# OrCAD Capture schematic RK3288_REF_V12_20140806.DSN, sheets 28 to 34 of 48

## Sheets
28 51.LCM-MIPI Panel (option): size A4; title: LCM-MIPI Panel (option); note: LCM-MIPI Panel (option)
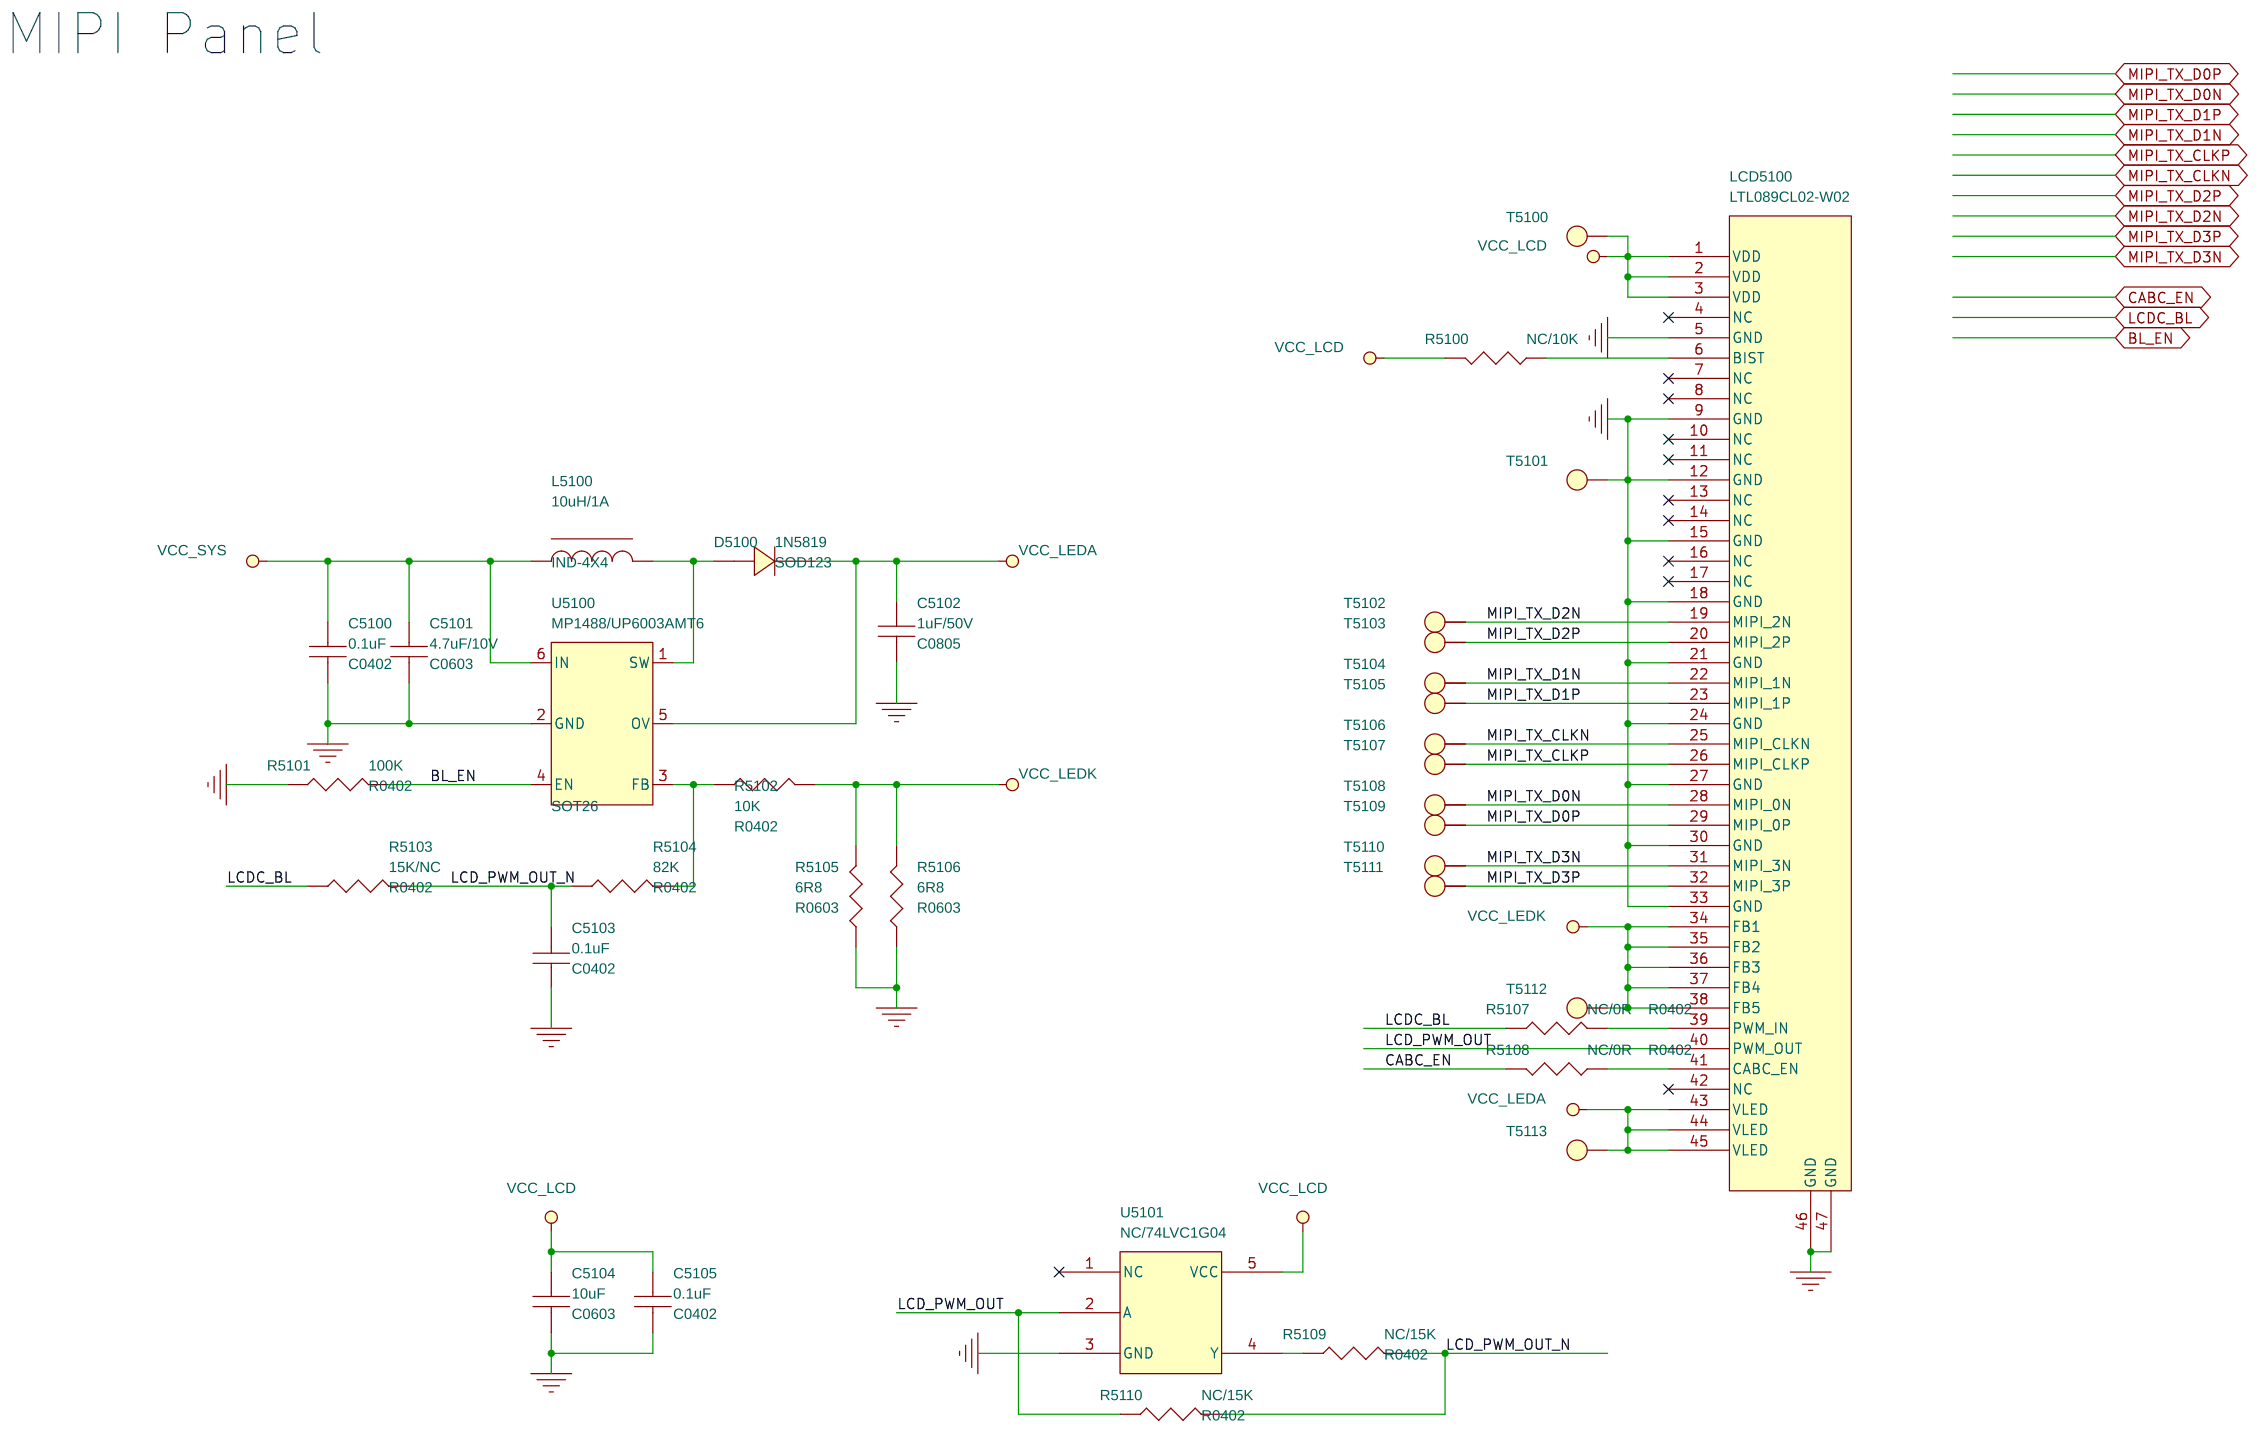
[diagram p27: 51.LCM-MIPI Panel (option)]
29 52.LCM-Dual MIPI Panel (option): size A4; title: LCM-Dual MIPI Panel (option); note: LCM-Dual MIPI Panel (option)
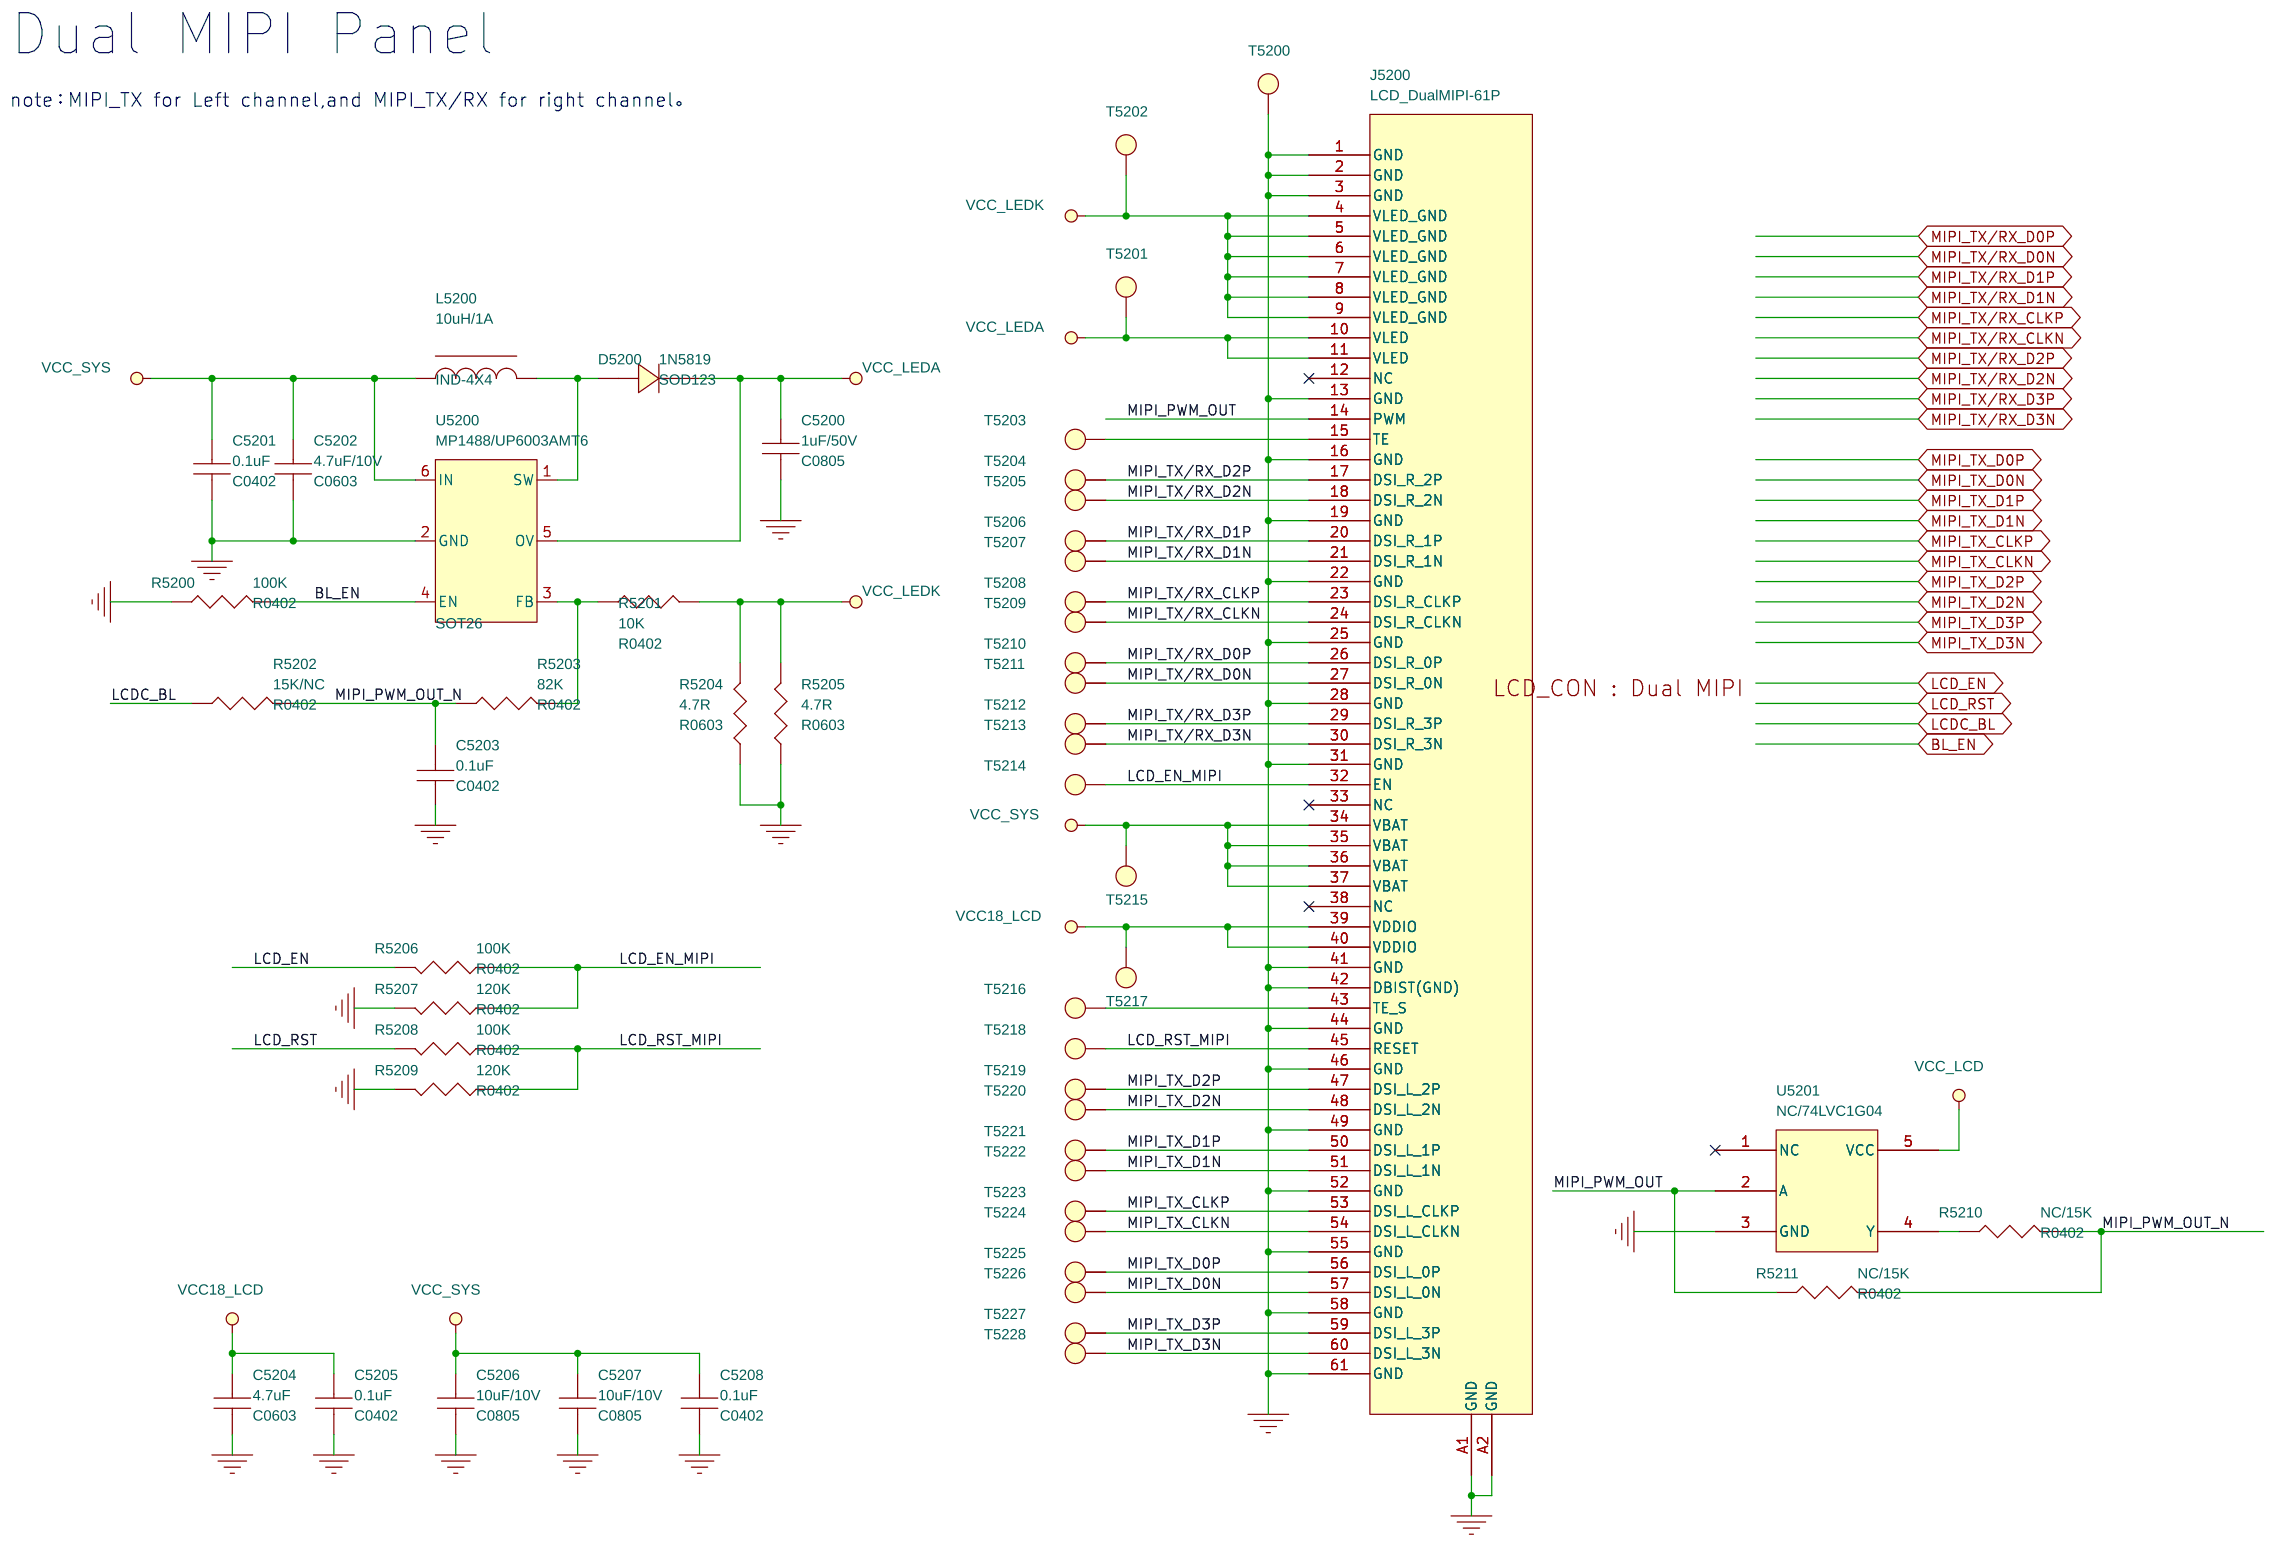
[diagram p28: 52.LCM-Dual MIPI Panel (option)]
30 53.LCM-LVDS Panel (option): size A4; title: LCM-LVDS Panel (option); note: LCM-LVDS Panel (option)
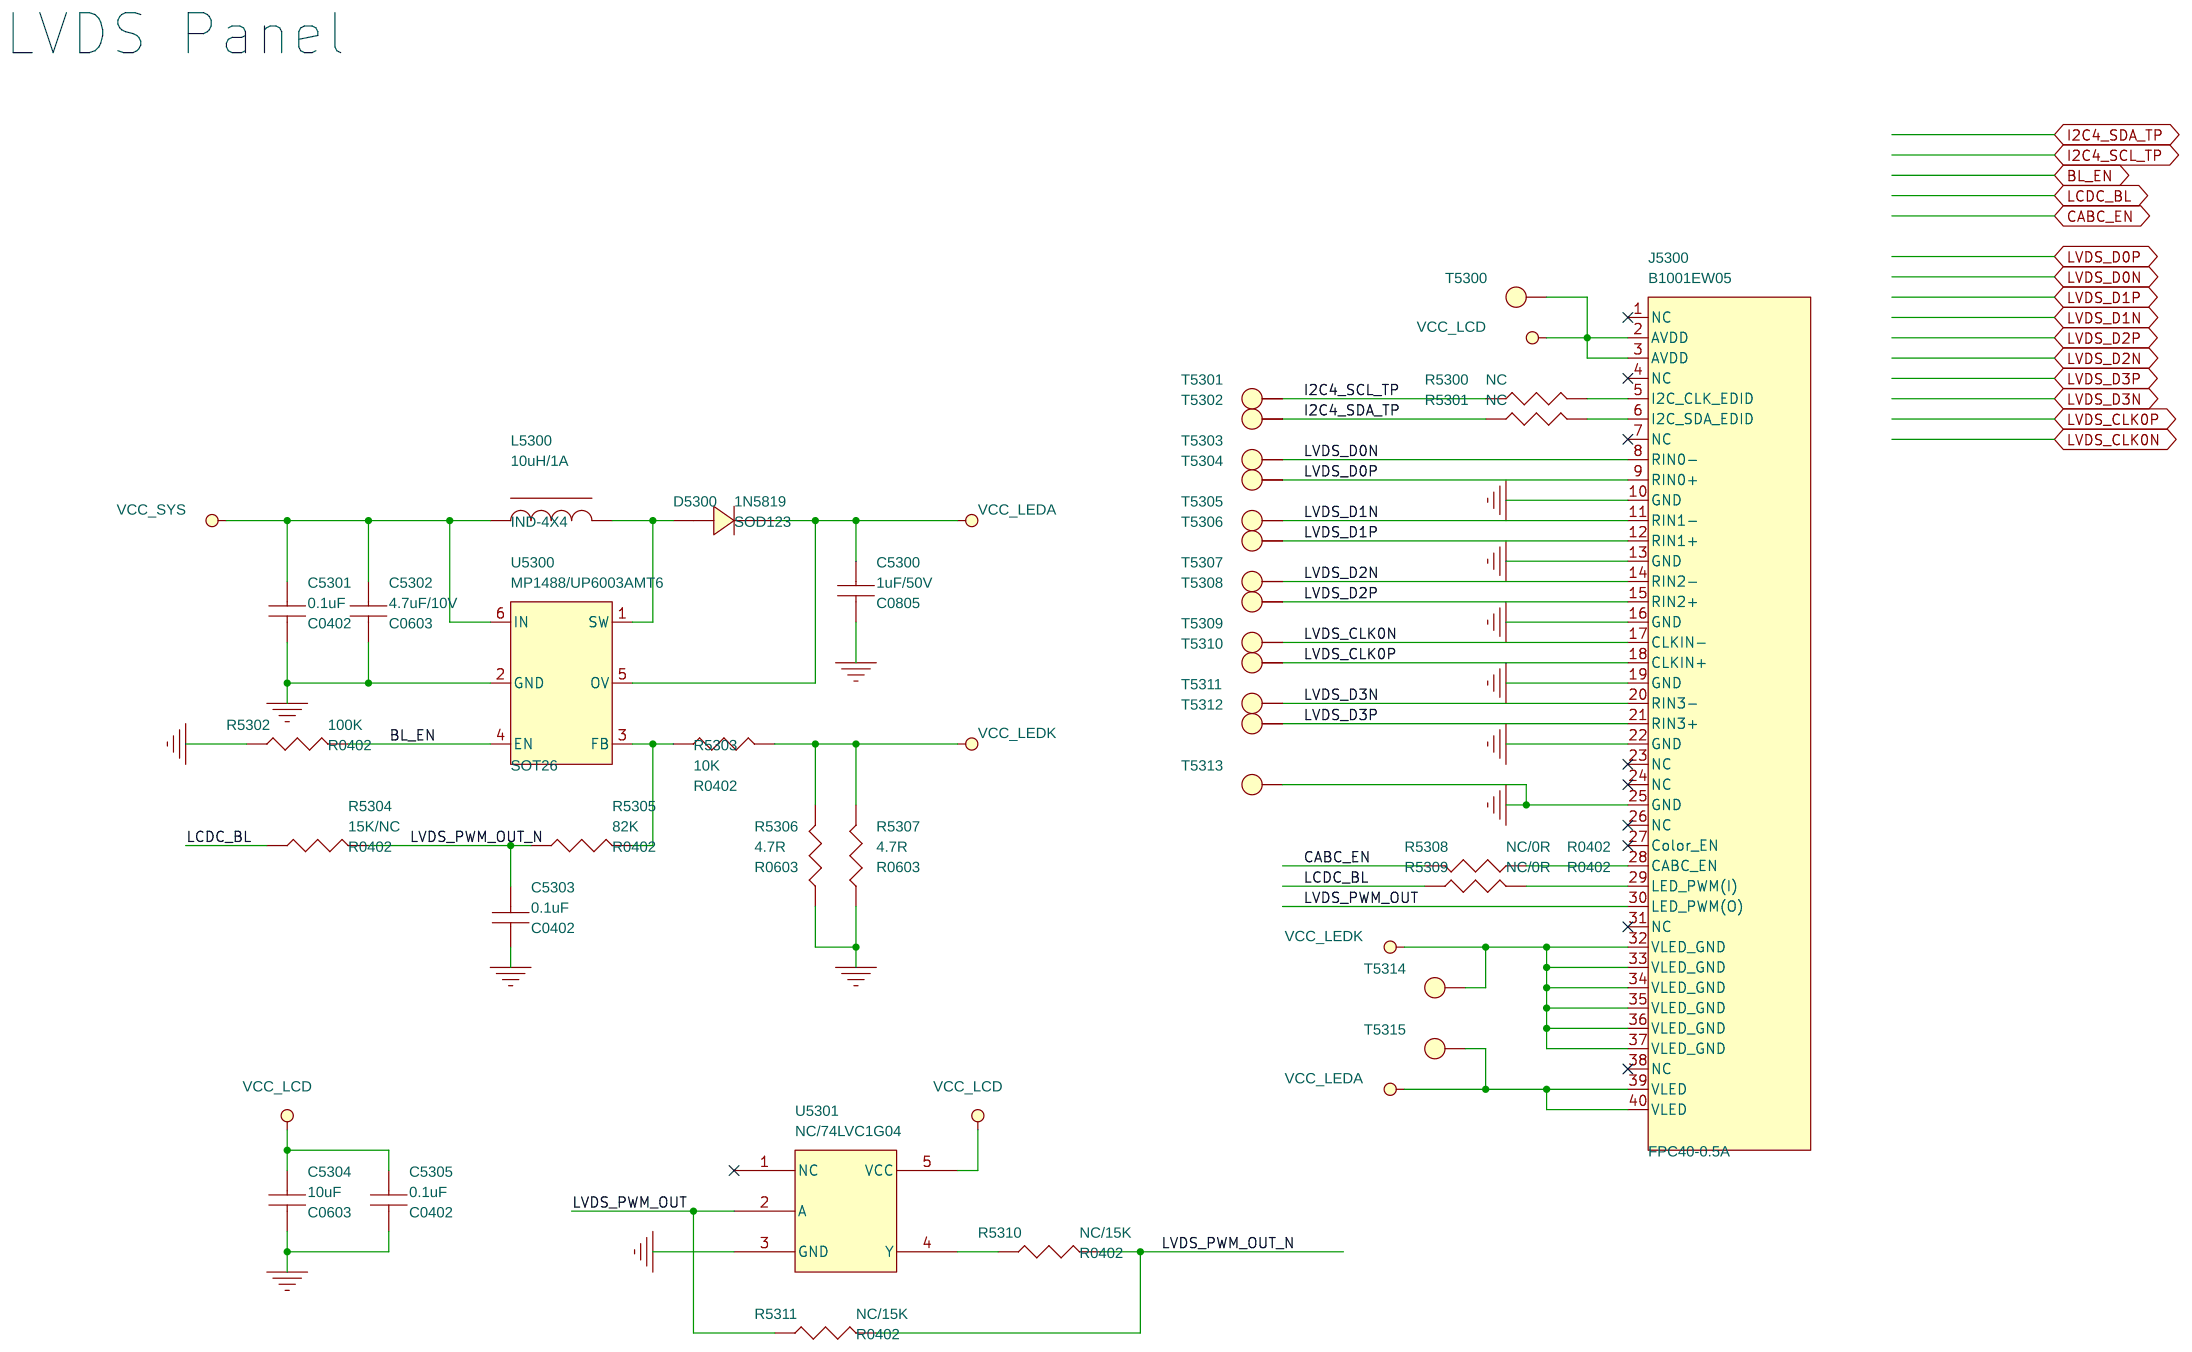
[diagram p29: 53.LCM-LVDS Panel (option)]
31 65.3G-UNA: size A3; title: 3G-UNA; note: 3G-UNA
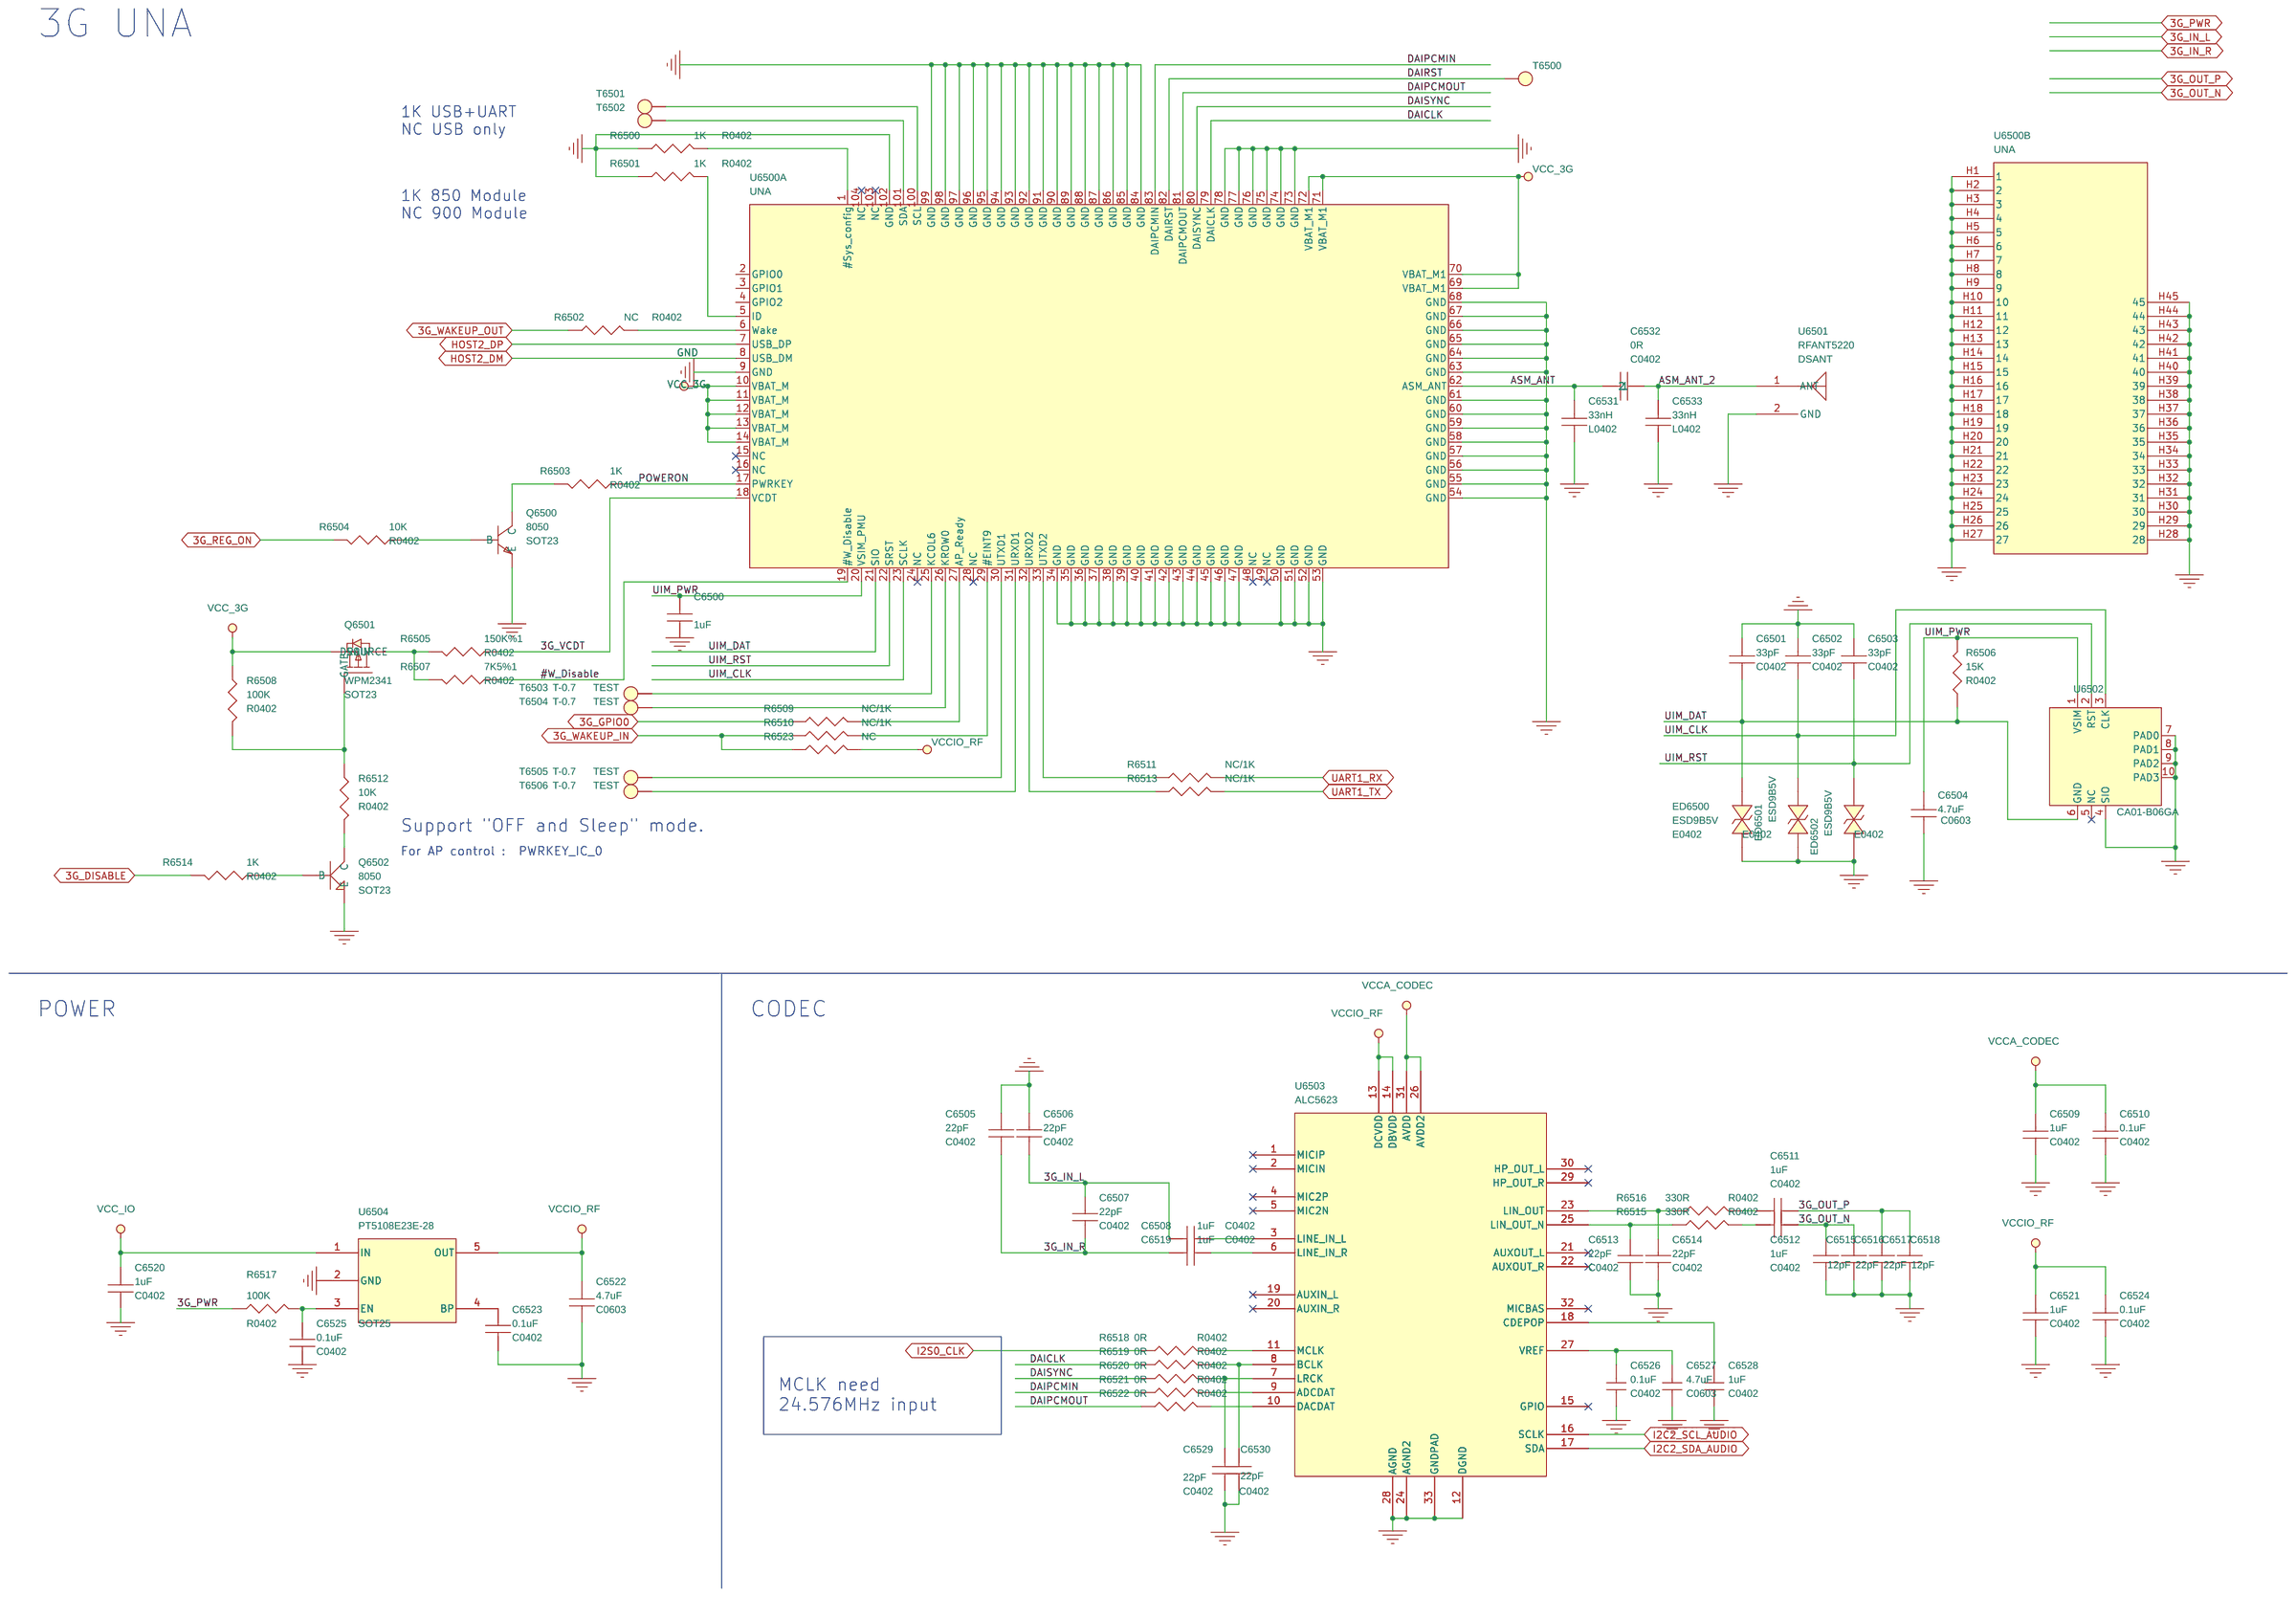
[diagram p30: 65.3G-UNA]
32 66.3G-UNA LITE (option): size A3; title: 3G-UNA LITE (option); note: 3G-UNA LITE (option)
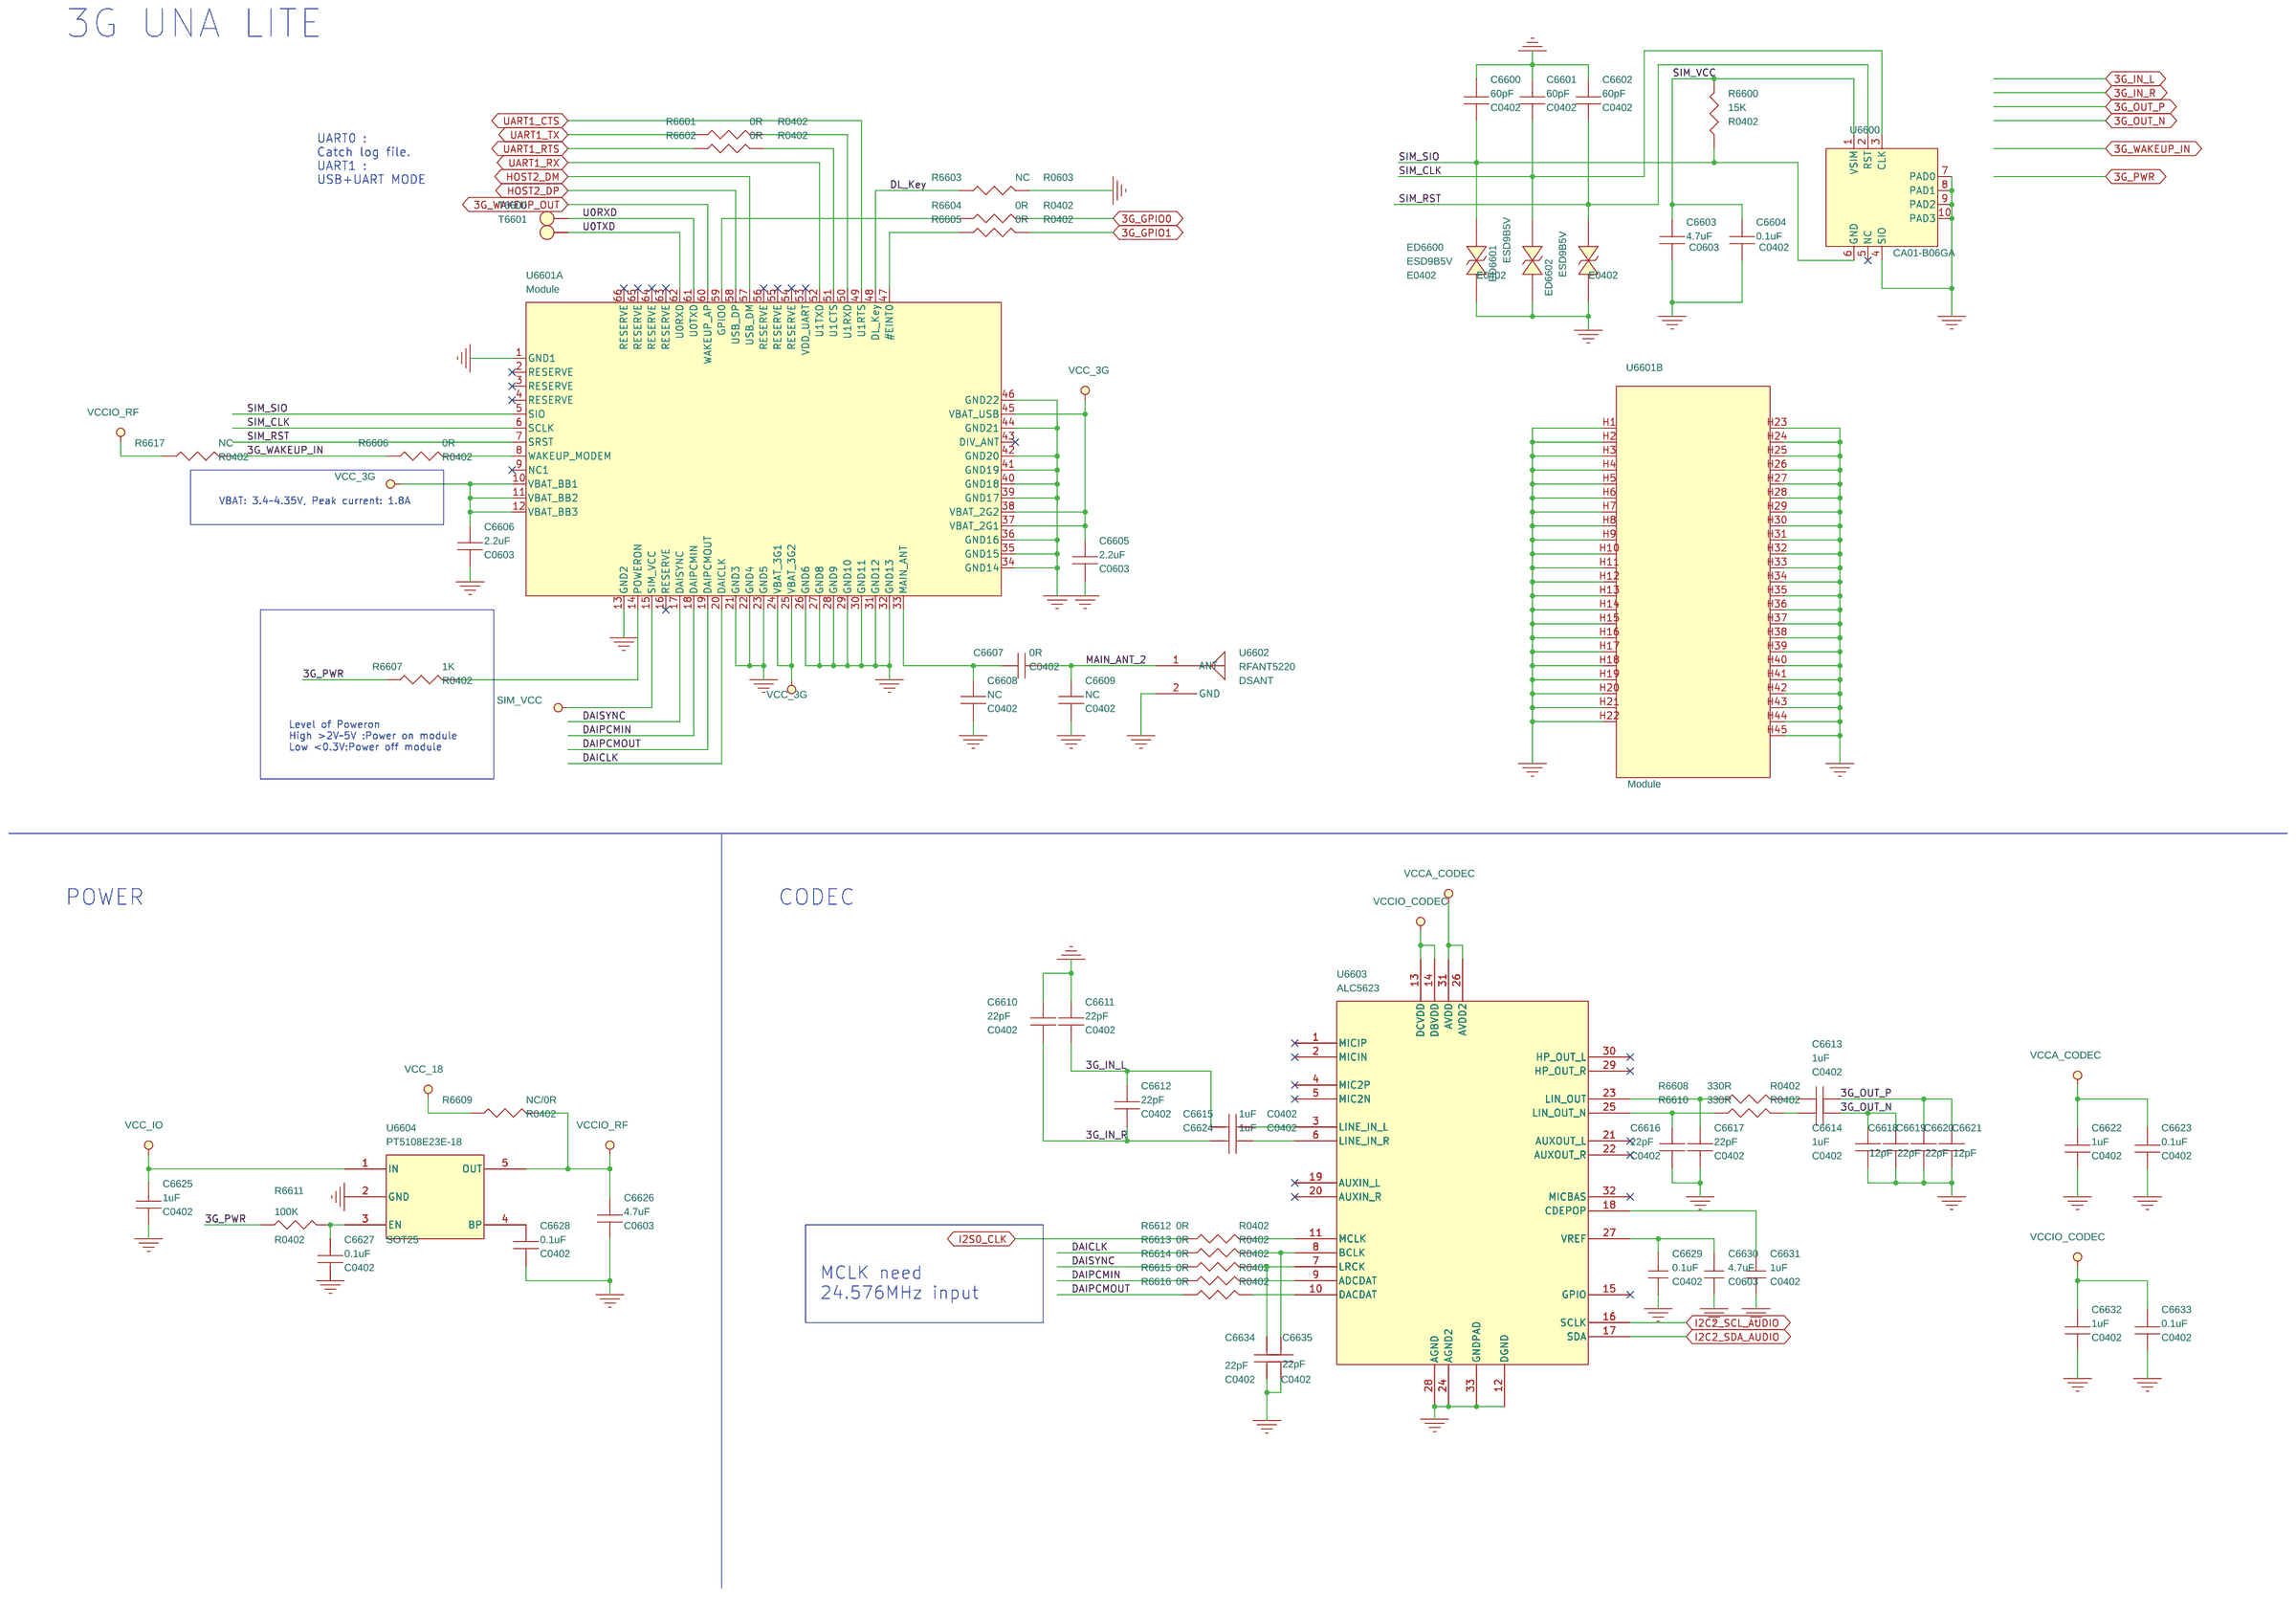
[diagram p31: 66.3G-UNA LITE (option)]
33 70.Audio Codec-ES8323: size A3; title: Audio Codec-ES8323; note: Audio Codec-ES8323
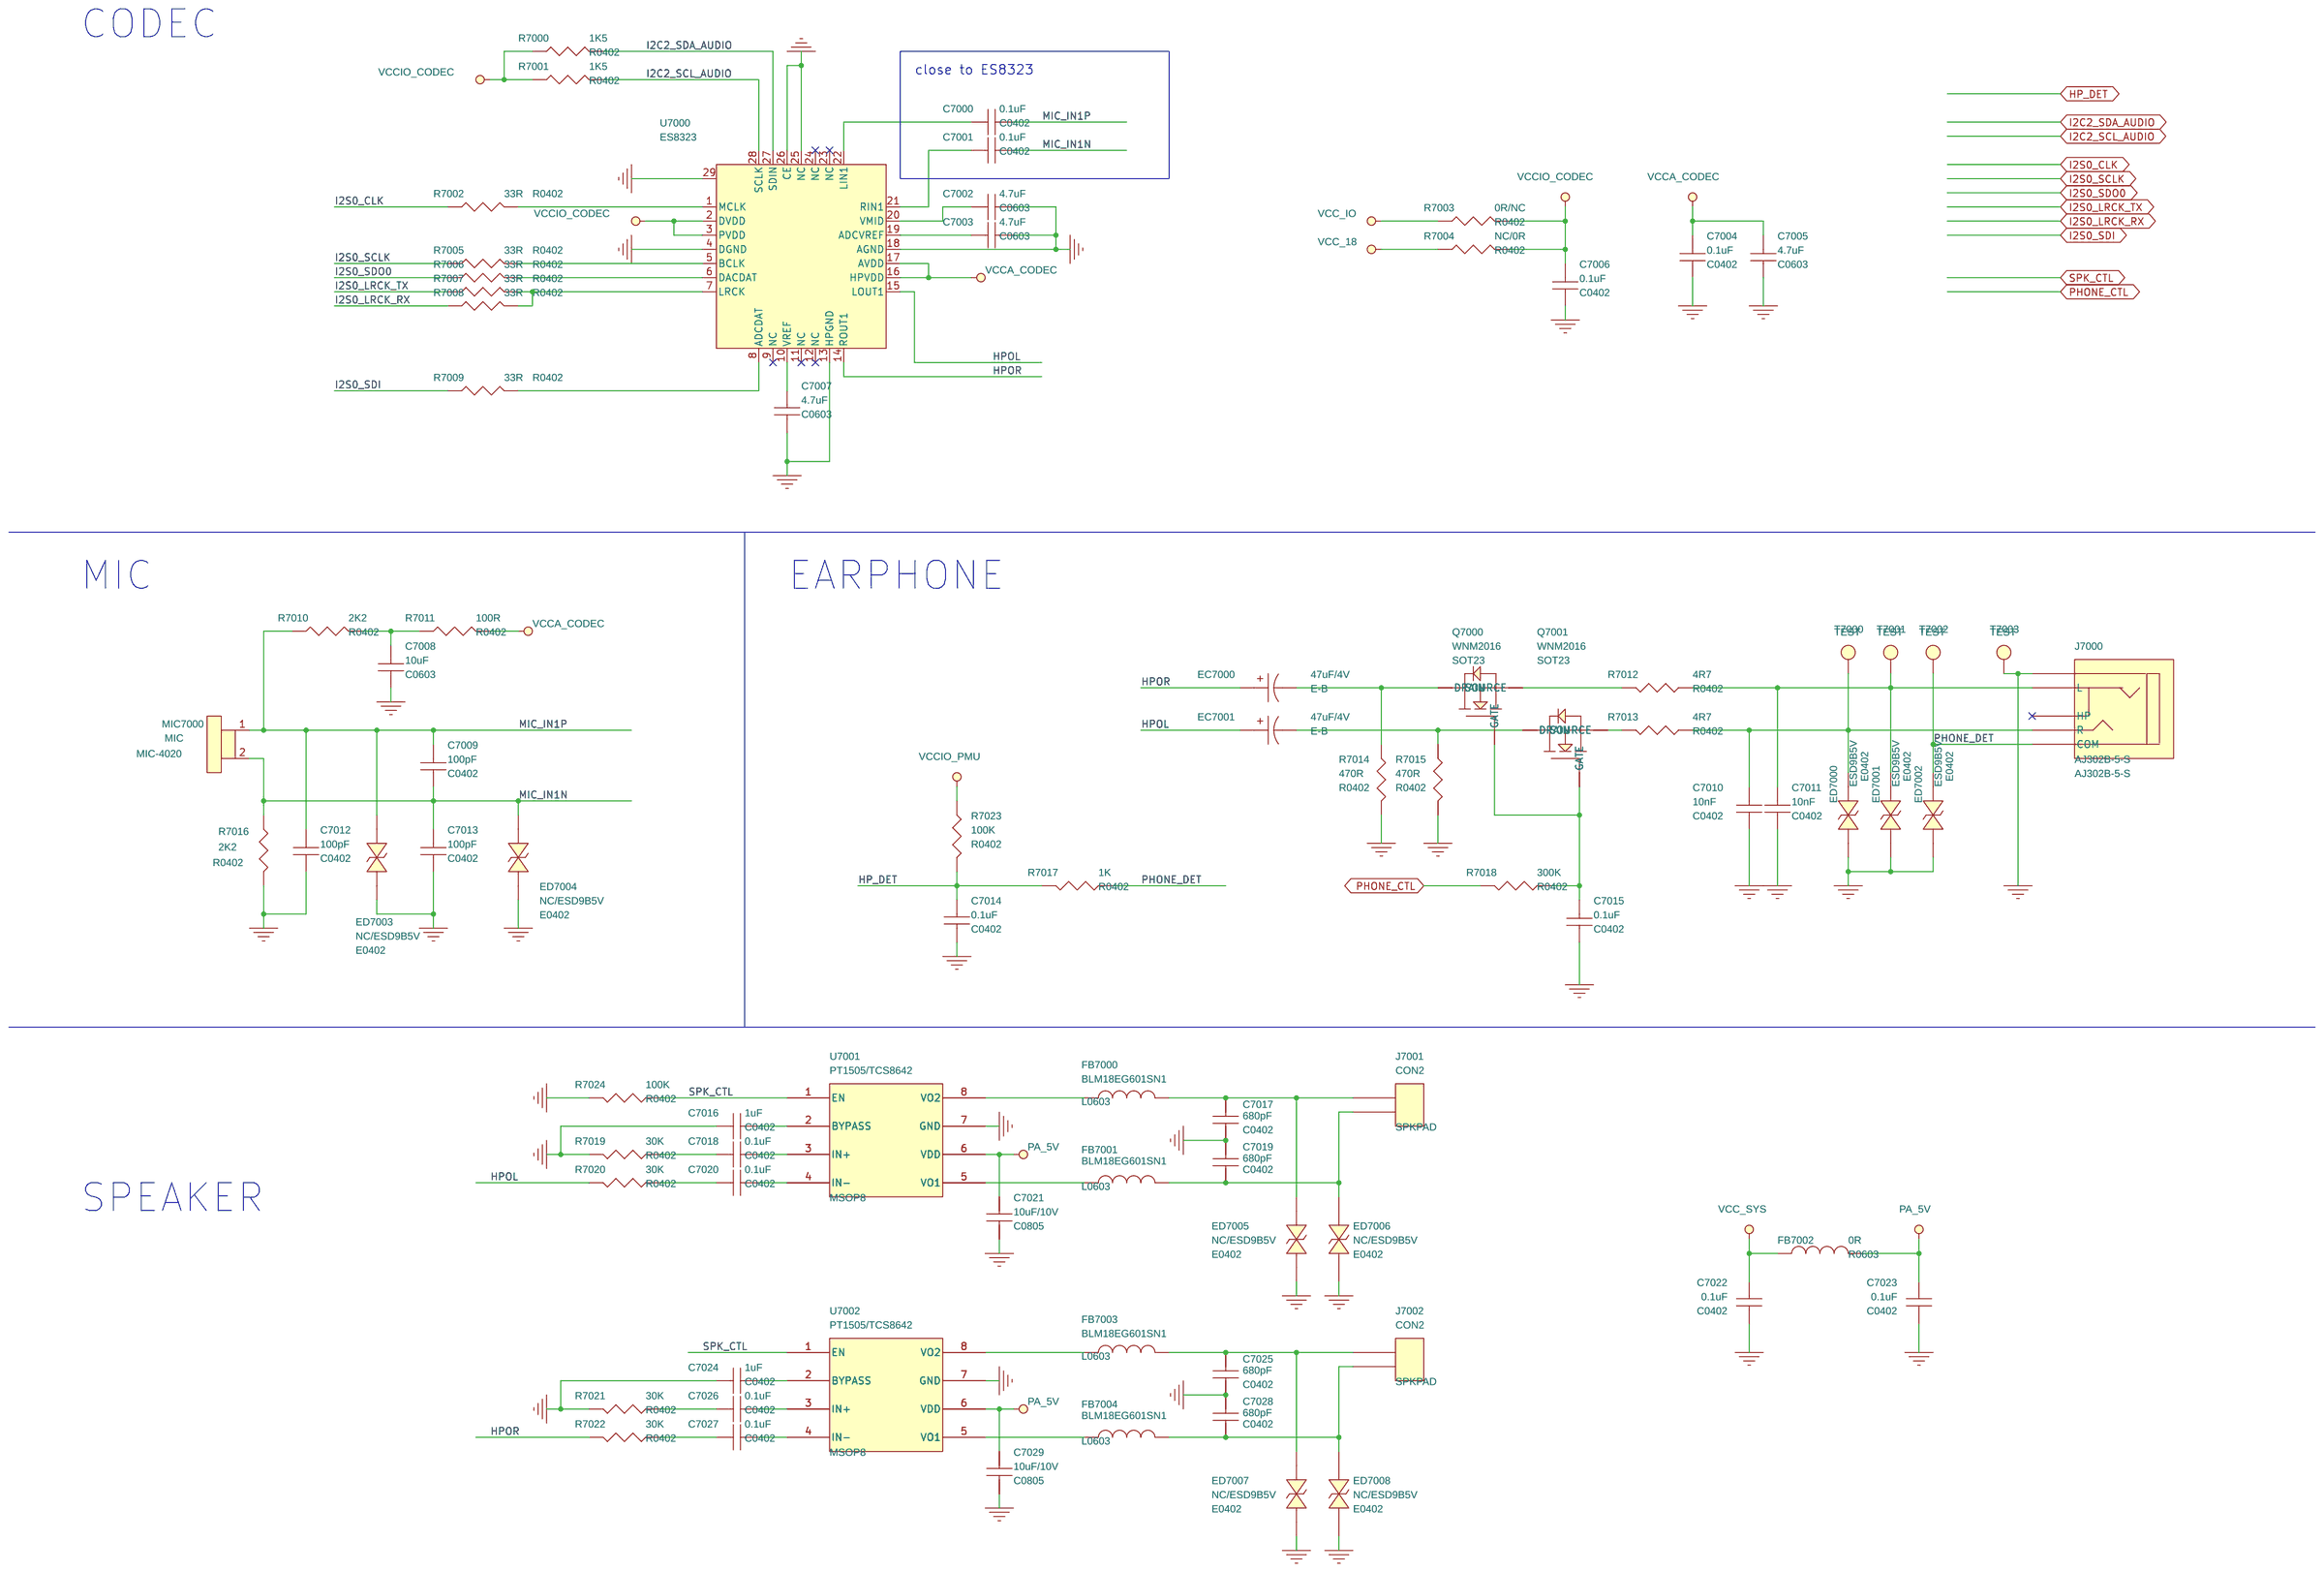
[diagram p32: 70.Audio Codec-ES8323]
34 71.Audio Codec-ALC5631 (option): size A3; title: Audio Codec-ALC5631 (option); note: Audio Codec-ALC5631Q
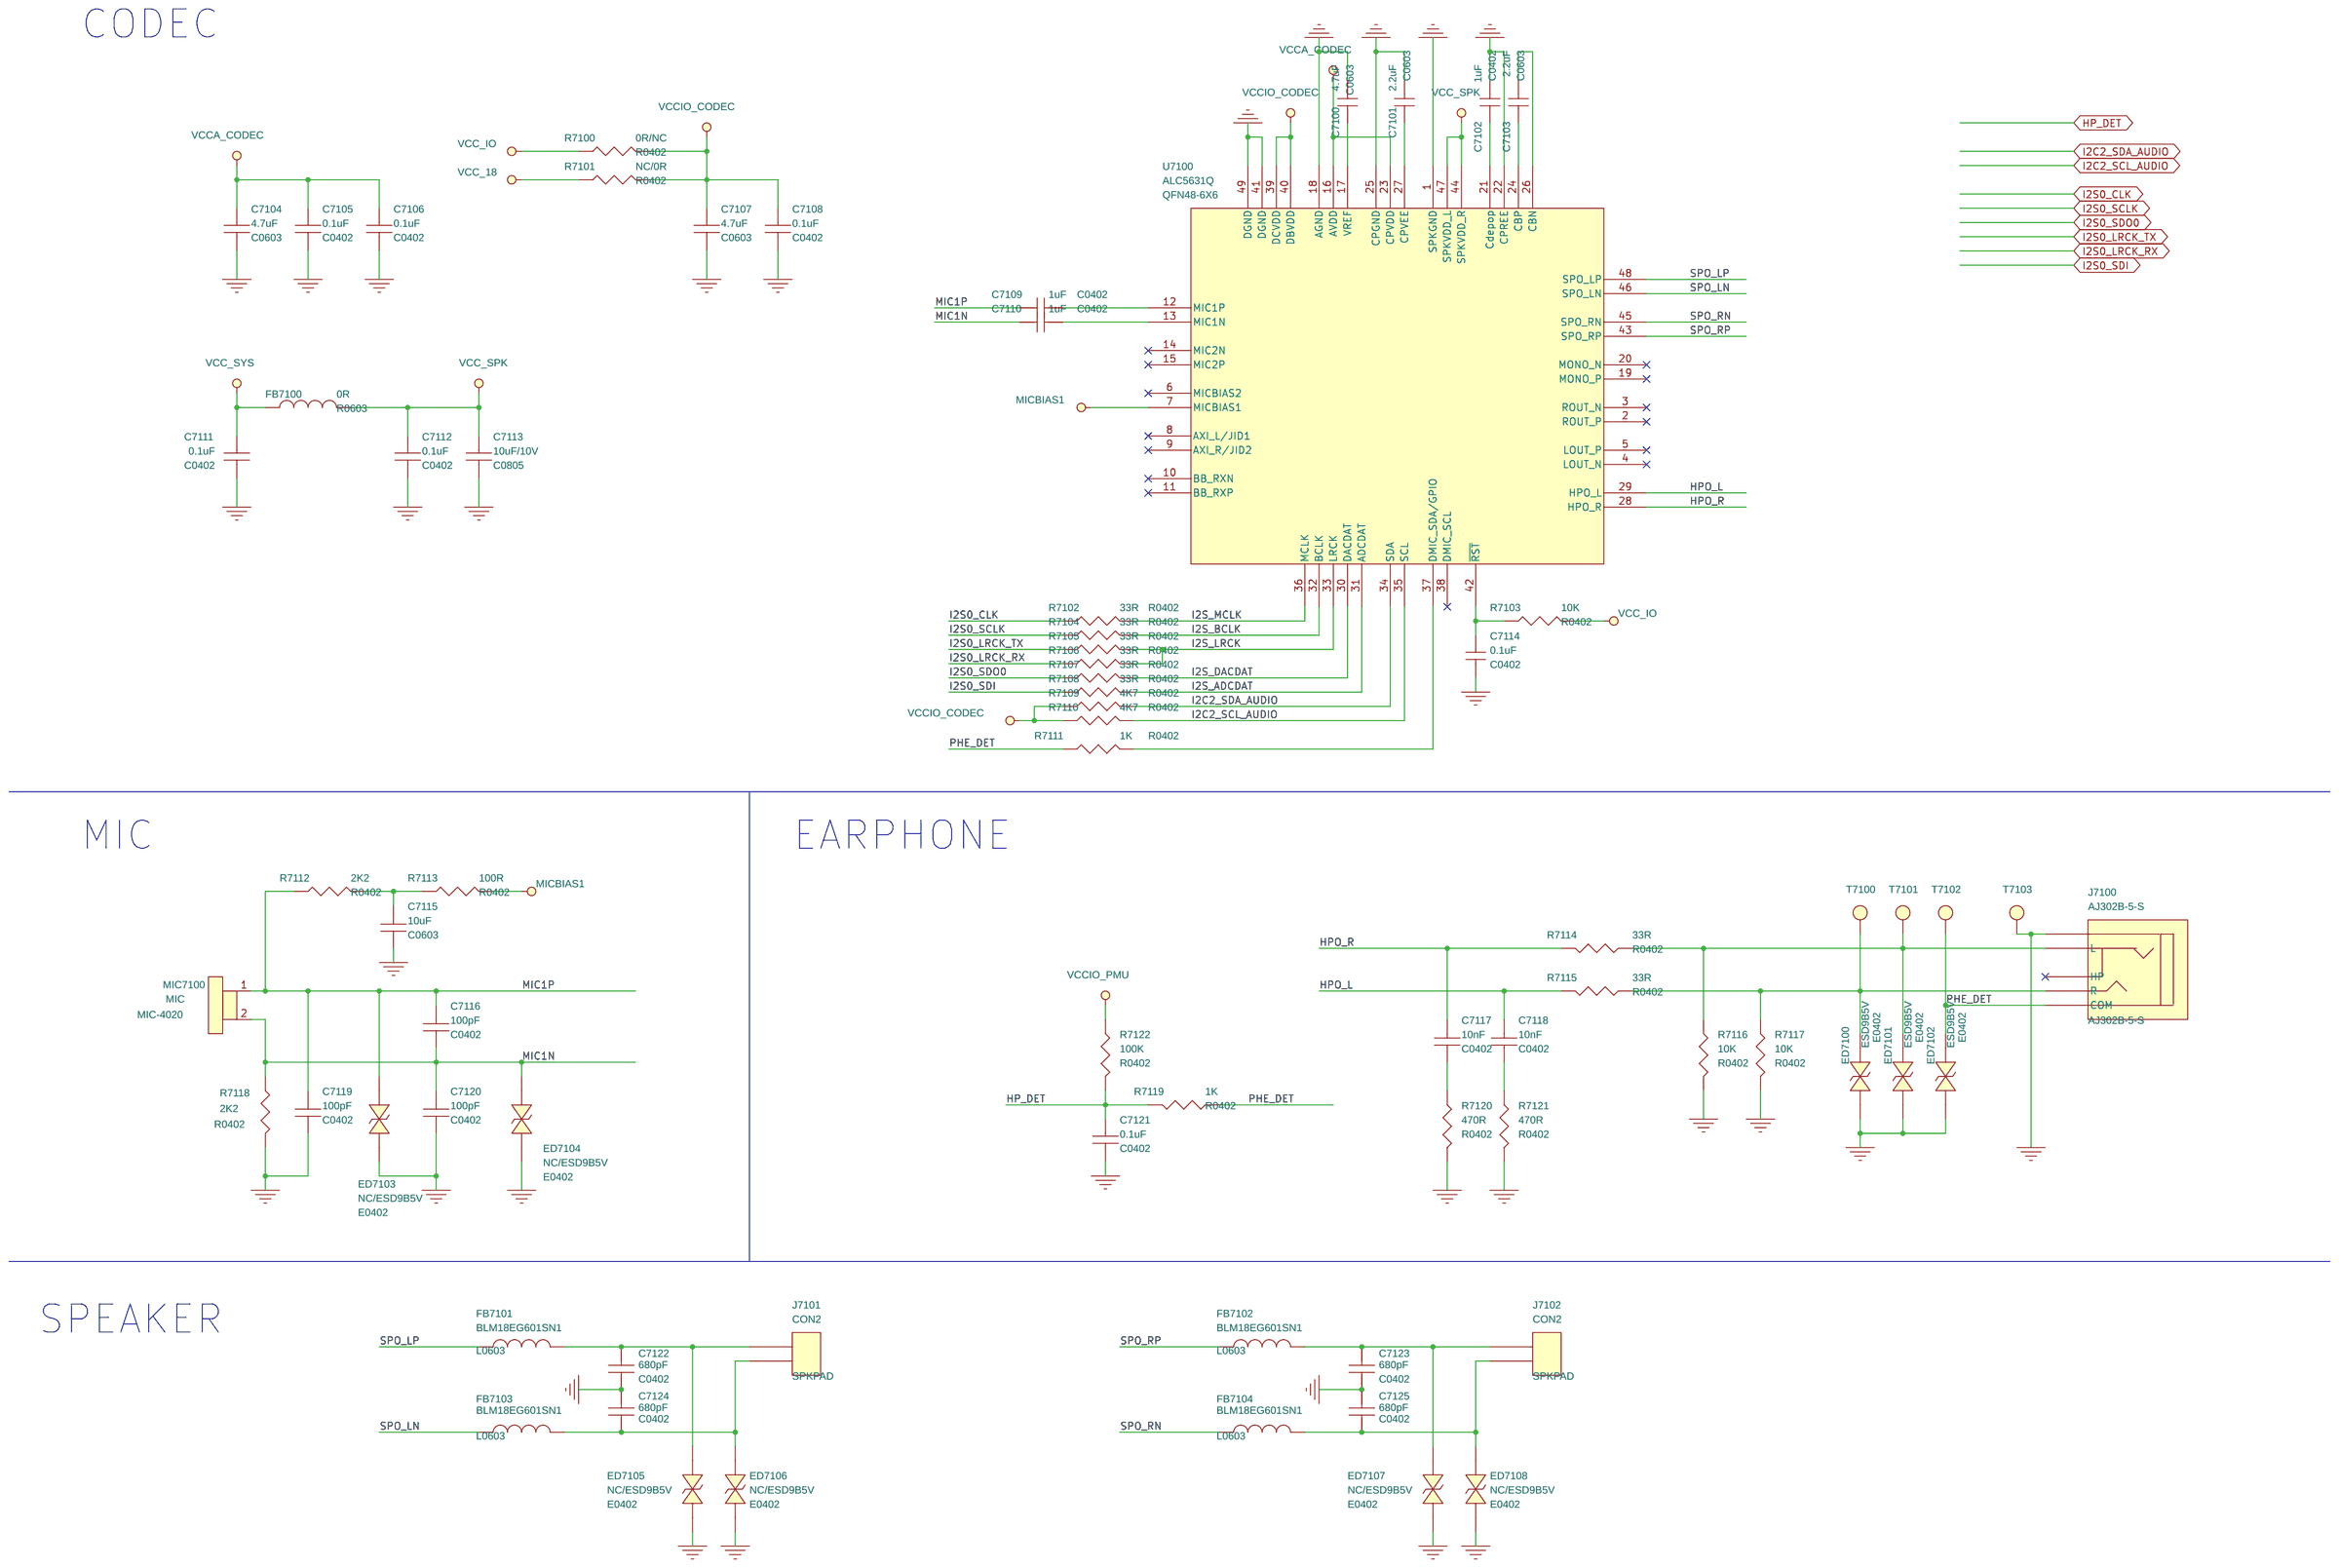
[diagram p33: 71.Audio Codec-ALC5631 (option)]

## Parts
sheet 51.LCM-MIPI Panel (option)
C5100  0.1uF  [C0402]
C5101  4.7uF/10V  [C0603]
C5102  1uF/50V  [C0805]
C5103  0.1uF  [C0402]
C5104  10uF  [C0603]
C5105  0.1uF  [C0402]
D5100  1N5819  [SOD123]
L5100  10uH/1A  [IND-4X4]
LCD5100  LTL089CL02-W02  [FH26-45S-0.3SHW]
R5100  NC/10K  [R0402]
R5101  100K  [R0402]
R5102  10K  [R0402]
R5103  15K/NC  [R0402]
R5104  82K  [R0402]
R5105  6R8  [R0603]
R5106  6R8  [R0603]
R5107  NC/0R  [R0402]
R5108  NC/0R  [R0402]
R5109  NC/15K  [R0402]
R5110  NC/15K  [R0402]
T5100  TEST  [T-0.7]
T5101  TEST  [T-0.7]
T5102  TEST  [T-0.7]
T5103  TEST  [T-0.7]
T5104  TEST  [T-0.7]
T5105  TEST  [T-0.7]
T5106  TEST  [T-0.7]
T5107  TEST  [T-0.7]
T5108  TEST  [T-0.7]
T5109  TEST  [T-0.7]
T5110  TEST  [T-0.7]
T5111  TEST  [T-0.7]
T5112  TEST  [T-0.7]
T5113  TEST  [T-0.7]
U5100  MP1488/UP6003AMT6  [SOT26]
U5101  NC/74LVC1G04  [SOT-23-6]
sheet 52.LCM-Dual MIPI Panel (option)
C5200  1uF/50V  [C0805]
C5201  0.1uF  [C0402]
C5202  4.7uF/10V  [C0603]
C5203  0.1uF  [C0402]
C5204  4.7uF  [C0603]
C5205  0.1uF  [C0402]
C5206  10uF/10V  [C0805]
C5207  10uF/10V  [C0805]
C5208  0.1uF  [C0402]
D5200  1N5819  [SOD123]
J5200  LCD_DualMIPI-61P  [FH36W-61S-0.3SHW]
L5200  10uH/1A  [IND-4X4]
R5200  100K  [R0402]
R5201  10K  [R0402]
R5202  15K/NC  [R0402]
R5203  82K  [R0402]
R5204  4.7R  [R0603]
R5205  4.7R  [R0603]
R5206  100K  [R0402]
R5207  120K  [R0402]
R5208  100K  [R0402]
R5209  120K  [R0402]
R5210  NC/15K  [R0402]
R5211  NC/15K  [R0402]
T5200  TEST  [T-0.7]
T5201  TEST  [T-0.7]
T5202  TEST  [T-0.7]
T5203  TEST  [T-0.7]
T5204  TEST  [T-0.7]
T5205  TEST  [T-0.7]
T5206  TEST  [T-0.7]
T5207  TEST  [T-0.7]
T5208  TEST  [T-0.7]
T5209  TEST  [T-0.7]
T5210  TEST  [T-0.7]
T5211  TEST  [T-0.7]
T5212  TEST  [T-0.7]
T5213  TEST  [T-0.7]
T5214  TEST  [T-0.7]
T5215  TEST  [T-0.7]
T5216  TEST  [T-0.7]
T5217  TEST  [T-0.7]
T5218  TEST  [T-0.7]
T5219  TEST  [T-0.7]
T5220  TEST  [T-0.7]
T5221  TEST  [T-0.7]
T5222  TEST  [T-0.7]
T5223  TEST  [T-0.7]
T5224  TEST  [T-0.7]
T5225  TEST  [T-0.7]
T5226  TEST  [T-0.7]
T5227  TEST  [T-0.7]
T5228  TEST  [T-0.7]
U5200  MP1488/UP6003AMT6  [SOT26]
U5201  NC/74LVC1G04  [SOT-23-6]
sheet 53.LCM-LVDS Panel (option)
C5300  1uF/50V  [C0805]
C5301  0.1uF  [C0402]
C5302  4.7uF/10V  [C0603]
C5303  0.1uF  [C0402]
C5304  10uF  [C0603]
C5305  0.1uF  [C0402]
D5300  1N5819  [SOD123]
J5300  B1001EW05  [FPC40-0.5A]
L5300  10uH/1A  [IND-4X4]
R5300  NC  [R0402]
R5301  NC  [R0402]
R5302  100K  [R0402]
R5303  10K  [R0402]
R5304  15K/NC  [R0402]
R5305  82K  [R0402]
R5306  4.7R  [R0603]
R5307  4.7R  [R0603]
R5308  NC/0R  [R0402]
R5309  NC/0R  [R0402]
R5310  NC/15K  [R0402]
R5311  NC/15K  [R0402]
T5300  TEST  [T-0.7]
T5301  TEST  [T-0.7]
T5302  TEST  [T-0.7]
T5303  TEST  [T-0.7]
T5304  TEST  [T-0.7]
T5305  TEST  [T-0.7]
T5306  TEST  [T-0.7]
T5307  TEST  [T-0.7]
T5308  TEST  [T-0.7]
T5309  TEST  [T-0.7]
T5310  TEST  [T-0.7]
T5311  TEST  [T-0.7]
T5312  TEST  [T-0.7]
T5313  TEST  [T-0.7]
T5314  TEST  [T-0.7]
T5315  TEST  [T-0.7]
U5300  MP1488/UP6003AMT6  [SOT26]
U5301  NC/74LVC1G04  [SOT-23-6]
sheet 65.3G-UNA
C6500  1uF  [C0402]
C6501  33pF  [C0402]
C6502  33pF  [C0402]
C6503  33pF  [C0402]
C6504  4.7uF  [C0603]
C6505  22pF  [C0402]
C6506  22pF  [C0402]
C6507  22pF  [C0402]
C6508  1uF  [C0402]
C6509  1uF  [C0402]
C6510  0.1uF  [C0402]
C6511  1uF  [C0402]
C6512  1uF  [C0402]
C6513  22pF  [C0402]
C6514  22pF  [C0402]
C6515  12pF  [C0402]
C6516  22pF  [C0402]
C6517  22pF  [C0402]
C6518  12pF  [C0402]
C6519  1uF  [C0402]
C6520  1uF  [C0402]
C6521  1uF  [C0402]
C6522  4.7uF  [C0603]
C6523  0.1uF  [C0402]
C6524  0.1uF  [C0402]
C6525  0.1uF  [C0402]
C6526  0.1uF  [C0402]
C6527  4.7uF  [C0603]
C6528  1uF  [C0402]
C6529  22pF  [C0402]
C6530  22pF  [C0402]
C6531  33nH  [L0402]
C6532  0R  [C0402]
C6533  33nH  [L0402]
ED6500  ESD9B5V  [E0402]
ED6501  ESD9B5V  [E0402]
ED6502  ESD9B5V  [E0402]
Q6500  8050  [SOT23]
Q6501  WPM2341  [SOT23]
Q6502  8050  [SOT23]
R6500  1K  [R0402]
R6501  1K  [R0402]
R6502  NC  [R0402]
R6503  1K  [R0402]
R6504  10K  [R0402]
R6505  150K%1  [R0402]
R6506  15K  [R0402]
R6507  7K5%1  [R0402]
R6508  100K  [R0402]
R6509  NC/1K  [R0402]
R6510  NC/1K  [R0402]
R6511  NC/1K  [R0402]
R6512  10K  [R0402]
R6513  NC/1K  [R0402]
R6514  1K  [R0402]
R6515  330R  [R0402]
R6516  330R  [R0402]
R6517  100K  [R0402]
R6518  0R  [R0402]
R6519  0R  [R0402]
R6520  0R  [R0402]
R6521  0R  [R0402]
R6522  0R  [R0402]
R6523  NC  [R0402]
T6500  TEST  [T-0.7]
T6501  TEST  [T-0.7]
T6502  TEST  [T-0.7]
T6503  TEST  [T-0.7]
T6504  TEST  [T-0.7]
T6505  TEST  [T-0.7]
T6506  TEST  [T-0.7]
U6500  UNA  [UNA_A]  (sections A,B)
U6501  RFANT5220  [DSANT]
U6502  CA01-B06GA  [SIM6P254_h20]
U6503  ALC5623  [ALC5623]
U6504  PT5108E23E-28  [SOT25]
sheet 66.3G-UNA LITE (option)
C6600  60pF  [C0402]
C6601  60pF  [C0402]
C6602  60pF  [C0402]
C6603  4.7uF  [C0603]
C6604  0.1uF  [C0402]
C6605  2.2uF  [C0603]
C6606  2.2uF  [C0603]
C6607  0R  [C0402]
C6608  NC  [C0402]
C6609  NC  [C0402]
C6610  22pF  [C0402]
C6611  22pF  [C0402]
C6612  22pF  [C0402]
C6613  1uF  [C0402]
C6614  1uF  [C0402]
C6615  1uF  [C0402]
C6616  22pF  [C0402]
C6617  22pF  [C0402]
C6618  12pF  [C0402]
C6619  22pF  [C0402]
C6620  22pF  [C0402]
C6621  12pF  [C0402]
C6622  1uF  [C0402]
C6623  0.1uF  [C0402]
C6624  1uF  [C0402]
C6625  1uF  [C0402]
C6626  4.7uF  [C0603]
C6627  0.1uF  [C0402]
C6628  0.1uF  [C0402]
C6629  0.1uF  [C0402]
C6630  4.7uF  [C0603]
C6631  1uF  [C0402]
C6632  1uF  [C0402]
C6633  0.1uF  [C0402]
C6634  22pF  [C0402]
C6635  22pF  [C0402]
ED6600  ESD9B5V  [E0402]
ED6601  ESD9B5V  [E0402]
ED6602  ESD9B5V  [E0402]
R6600  15K  [R0402]
R6601  0R  [R0402]
R6602  0R  [R0402]
R6603  NC  [R0603]
R6604  0R  [R0402]
R6605  0R  [R0402]
R6606  0R  [R0402]
R6607  1K  [R0402]
R6608  330R  [R0402]
R6609  NC/0R  [R0402]
R6610  330R  [R0402]
R6611  100K  [R0402]
R6612  0R  [R0402]
R6613  0R  [R0402]
R6614  0R  [R0402]
R6615  0R  [R0402]
R6616  0R  [R0402]
R6617  NC  [R0402]
T6600  TEST  [T-0.7]
T6601  TEST  [T-0.7]
U6600  CA01-B06GA  [SIM6P254_h20]
U6601  Module  [LGA66_27x16_7mm_01]  (sections A,B)
U6602  RFANT5220  [DSANT]
U6603  ALC5623  [ALC5623]
U6604  PT5108E23E-18  [SOT25]
sheet 70.Audio Codec-ES8323
C7000  0.1uF  [C0402]
C7001  0.1uF  [C0402]
C7002  4.7uF  [C0603]
C7003  4.7uF  [C0603]
C7004  0.1uF  [C0402]
C7005  4.7uF  [C0603]
C7006  0.1uF  [C0402]
C7007  4.7uF  [C0603]
C7008  10uF  [C0603]
C7009  100pF  [C0402]
C7010  10nF  [C0402]
C7011  10nF  [C0402]
C7012  100pF  [C0402]
C7013  100pF  [C0402]
C7014  0.1uF  [C0402]
C7015  0.1uF  [C0402]
C7016  1uF  [C0402]
C7017  680pF  [C0402]
C7018  0.1uF  [C0402]
C7019  680pF  [C0402]
C7020  0.1uF  [C0402]
C7021  10uF/10V  [C0805]
C7022  0.1uF  [C0402]
C7023  0.1uF  [C0402]
C7024  1uF  [C0402]
C7025  680pF  [C0402]
C7026  0.1uF  [C0402]
C7027  0.1uF  [C0402]
C7028  680pF  [C0402]
C7029  10uF/10V  [C0805]
EC7000  47uF/4V  [E-B]
EC7001  47uF/4V  [E-B]
ED7000  ESD9B5V  [E0402]
ED7001  ESD9B5V  [E0402]
ED7002  ESD9B5V  [E0402]
ED7003  NC/ESD9B5V  [E0402]
ED7004  NC/ESD9B5V  [E0402]
ED7005  NC/ESD9B5V  [E0402]
ED7006  NC/ESD9B5V  [E0402]
ED7007  NC/ESD9B5V  [E0402]
ED7008  NC/ESD9B5V  [E0402]
FB7000  BLM18EG601SN1  [L0603]
FB7001  BLM18EG601SN1  [L0603]
FB7002  0R  [R0603]
FB7003  BLM18EG601SN1  [L0603]
FB7004  BLM18EG601SN1  [L0603]
J7000  AJ302B-5-S  [AJ302B-5-S]
J7001  CON2  [SPKPAD]
J7002  CON2  [SPKPAD]
MIC7000  MIC  [MIC-4020]
Q7000  WNM2016  [SOT23]
Q7001  WNM2016  [SOT23]
R7000  1K5  [R0402]
R7001  1K5  [R0402]
R7002  33R  [R0402]
R7003  0R/NC  [R0402]
R7004  NC/0R  [R0402]
R7005  33R  [R0402]
R7006  33R  [R0402]
R7007  33R  [R0402]
R7008  33R  [R0402]
R7009  33R  [R0402]
R7010  2K2  [R0402]
R7011  100R  [R0402]
R7012  4R7  [R0402]
R7013  4R7  [R0402]
R7014  470R  [R0402]
R7015  470R  [R0402]
R7016  2K2  [R0402]
R7017  1K  [R0402]
R7018  300K  [R0402]
R7019  30K  [R0402]
R7020  30K  [R0402]
R7021  30K  [R0402]
R7022  30K  [R0402]
R7023  100K  [R0402]
R7024  100K  [R0402]
T7000  TEST  [T-0.7]
T7001  TEST  [T-0.7]
T7002  TEST  [T-0.7]
T7003  TEST  [T-0.7]
U7000  ES8323  [WM8988]
U7001  PT1505/TCS8642  [MSOP8]
U7002  PT1505/TCS8642  [MSOP8]
sheet 71.Audio Codec-ALC5631 (option)
C7100  4.7uF  [C0603]
C7101  2.2uF  [C0603]
C7102  1uF  [C0402]
C7103  2.2uF  [C0603]
C7104  4.7uF  [C0603]
C7105  0.1uF  [C0402]
C7106  0.1uF  [C0402]
C7107  4.7uF  [C0603]
C7108  0.1uF  [C0402]
C7109  1uF  [C0402]
C7110  1uF  [C0402]
C7111  0.1uF  [C0402]
C7112  0.1uF  [C0402]
C7113  10uF/10V  [C0805]
C7114  0.1uF  [C0402]
C7115  10uF  [C0603]
C7116  100pF  [C0402]
C7117  10nF  [C0402]
C7118  10nF  [C0402]
C7119  100pF  [C0402]
C7120  100pF  [C0402]
C7121  0.1uF  [C0402]
C7122  680pF  [C0402]
C7123  680pF  [C0402]
C7124  680pF  [C0402]
C7125  680pF  [C0402]
ED7100  ESD9B5V  [E0402]
ED7101  ESD9B5V  [E0402]
ED7102  ESD9B5V  [E0402]
ED7103  NC/ESD9B5V  [E0402]
ED7104  NC/ESD9B5V  [E0402]
ED7105  NC/ESD9B5V  [E0402]
ED7106  NC/ESD9B5V  [E0402]
ED7107  NC/ESD9B5V  [E0402]
ED7108  NC/ESD9B5V  [E0402]
FB7100  0R  [R0603]
FB7101  BLM18EG601SN1  [L0603]
FB7102  BLM18EG601SN1  [L0603]
FB7103  BLM18EG601SN1  [L0603]
FB7104  BLM18EG601SN1  [L0603]
J7100  AJ302B-5-S  [AJ302B-5-S]
J7101  CON2  [SPKPAD]
J7102  CON2  [SPKPAD]
MIC7100  MIC  [MIC-4020]
R7100  0R/NC  [R0402]
R7101  NC/0R  [R0402]
R7102  33R  [R0402]
R7103  10K  [R0402]
R7104  33R  [R0402]
R7105  33R  [R0402]
R7106  33R  [R0402]
R7107  33R  [R0402]
R7108  33R  [R0402]
R7109  4K7  [R0402]
R7110  4K7  [R0402]
R7111  1K  [R0402]
R7112  2K2  [R0402]
R7113  100R  [R0402]
R7114  33R  [R0402]
R7115  33R  [R0402]
R7116  10K  [R0402]
R7117  10K  [R0402]
R7118  2K2  [R0402]
R7119  1K  [R0402]
R7120  470R  [R0402]
R7121  470R  [R0402]
R7122  100K  [R0402]
T7100  TEST  [T-0.7]
T7101  TEST  [T-0.7]
T7102  TEST  [T-0.7]
T7103  TEST  [T-0.7]
U7100  ALC5631Q  [QFN48-6X6]

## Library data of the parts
C5100 C5105 C5201 C5301 C5305 C6523 C6525 C6627 C6628 = CAP_NP: CAP,MLCC,100nF,+/-10%,X7R,6.3V,SMD0402
C5101 C5202 C5302 C6531 C6533 C6605-C6609 C7008 C7115 = CAP_NP
C5102 C5200 C5300 = CAP_NP: RoHS CHIP CAP 1uF +10/-10% 25V X5R
C5103 C5203-C5208 C5303 C7004 C7014 C7015 C7018 C7020 C7022 C7023 C7026 C7027 C7104-C7108 C7111-C7113 C7121 = CAP_NP: RoHS CHIP CAP 0.1uF +10/-10% X7R
C5104 C5304 = CAP_NP: CAP,MLCC,4.7uF,+/-10%,X5R,6.3V,SMD0603
D5100 D5200 D5300 = DIODE
L5100 L5200 L5300 = INDUCTORS_OF_FERRITE
LCD5100 = LD089WU1_0
R5100 R5108 R5308 = RESISTOR: NC
R5101 R5103 R5104 R5107 R5109 R5110 R5200 R5202 R5203 R5206-R5211 R5302 R5304 R5305 R5309-R5311 = RES_1B: ROHS CHIP RES 4.7K 1/16W 5%
R5102 R5201 R5303 = RES_1B: ROHS CHIP RES 82K 1/16W 5%
R5105 R5106 R5204 R5205 R5306 R5307 = RES_1B: ROHS CHIP RES 4.7R 1/4W 5%
T5100-T5113 T5200-T5228 T5300-T5315 T6503-T6506 T6600 T6601 T7000-T7003 T7100-T7103 = TESTPOINT1
U5100 U5200 U5300 = LED_Drive-BL: MP1488/UP6003AMT6  Fixed Frequency White LED Driver
U5101 U5201 U5301 = Inverter-74LVC1G04
J5200 = LCD_Dual_MIPI-61P
J5300 = AUO--LCD_0
R5300 R5301 = RESISTOR: ROHS CHIP RES 33 Ohm 1/16W +/-5%
C6500 = CAP_NP: RoHS CHIP CAP 0.1uF +10/-10% X7R; MARK: 106; ROOM: USB+5V
C6501-C6503 C6600-C6602 = CAP_NP: RoHS CHIP CAP 33pF 1% NPO
C6504 C6603 C6604 C7002 C7003 C7007 = CAP_NP: RoHS CHIP CAP 4.7uF +10/-10% X5R
C6505-C6507 C6513-C6518 C6610-C6612 C6616-C6621 C7009 C7012 C7013 C7116 C7119 C7120 = CAP_NP: RoHS CHIP CAP 100pF +10/-10% X7R
C6508 C6519 C6615 C6624 = CAP_NP: RoHS CHIP CAP 1uF +10/-10% 16V X5R
C6509 C6510 C6521 C6524 C6622 C6623 C6632 C6633 C7006 = CAP_v2: RoHS CHIP CAP 0.1uF +10/-10% X7R
C6511 C6512 C6613 C6614 C7000 C7001 = CAP_NP: RoHS CHIP CAP 0.1uF +10/-10% 16V X5R
C6520 C6522 C6625 C6626 = CAP_NP: CAP,MLCC,10uF,+/-10%,X5R,6.3V,SMD0805
C6526 C6528 C6629 C6631 = SMALL_CAP: RoHS CHIP CAP 0.1uF +10/-10% X7R
C6527 C6630 = SMALL_CAP: RoHS CHIP CAP 4.7uF +10/-10% X5R
C6529 C6530 C6634 C6635 = CAP_NP: RoHS CHIP CAP 22pF +10/-10% X7R
C6532 = CAP
ED6500-ED6502 ED6600-ED6602 ED7000-ED7002 ED7100-ED7102 = TVS: ESD Component,5V,30P,SMD,0402
Q6500 = NPN
Q6501 = MOSFET_P_v3: MOSFET-P,WPM2026 ,-20V,+/-8V,-3.2A,56m Ohm@Vgs=-4.5V,69m Ohm@Vgs=-2.5V,86m Ohm@Vgs=-1.8V,SOT23; ROOM: CHG
Q6502 = NPN4
R6500 R6501 R6601-R6606 R6617 R7003 R7004 R7100 R7101 = RES_1B
R6502 R6607 = RESISTOR
R6503 R6504 = RESISTOR_0: ROHS CHIP RES 10K 1/16W +/-5%
R6505 R6507 R6508 R6512 R6514 = RESISTOR: RES,thick film,22Kohm,+/-5%,1/16W,SMD0402
R6506 R6600 = RESISTOR: ROHS CHIP RES 15K 1/16W 5%
R6509-R6511 R6513 R6523 = RESISTOR_0: ROHS CHIP RES 0R 1/16W 5%
R6515 R6516 R6608 R6610 = RESISTOR: ROHS CHIP RES 330R 1/16W 5%
R6517 R6609 R6611 R7016 R7118 = RESISTOR_0: 贴片电阻
R6518-R6522 R6612-R6616 = RESISTOR: ROHS CHIP RES 0R 1/16W 5%
T6500-T6502 = TESTPOINT1: BOM_TYPE: 99; BOM_VALUE: 0
U6500 = UNA_Module-open_frame
U6501 = ANT3
U6502 U6600 = CA01-B06GA
U6503 U6603 = CODEC_ALC5623: CODEC
U6504 U6604 = LDO-PT5108_RT9013: LDO,PT5108E23E-33,VINmax=5.5V,Vout=3.3V,+/-2%,500mA,SOT-23-5
U6601 = 3G-UNA-PLUS
U6602 = ANT3: ANT
C7005 = CAP_NP: RoHS CHIP CAP 2.2uF +10/-10% X5R
C7010 C7011 C7117 C7118 = CAP_NP: RoHS CHIP CAP 0.47uF +10/-10% X5R
C7016 C7024 = CAP_NP: RoHS CHIP CAP 1uF +10/-10% X5R
C7017 C7019 C7025 C7028 C7122-C7125 = CAP_NP: CAP,MLCC,680pF,+/-10%,NPO,6.3V,SMD0402
C7021 C7029 = CAP_NP: RoHS CHIP CAP 10uF +10/-10% X5R; MARK: 106; ROOM: USB+5V
EC7000 EC7001 = CAP_POL: TAN CAP,47uF,+/-10%,4V,3.5mm*2.8mm*1.9mm,SMD-3528
ED7003 ED7004 ED7103 ED7104 = DIODE_BI-DIR_TRIG: ESD
ED7005-ED7008 ED7105-ED7108 = DIODE_BI-DIR_TRIG: NC/ESD Component,5V,30P,SMD,0402
FB7000 FB7001 FB7003 FB7004 FB7101-FB7104 = INDUCTOR: FB,Multilayer,180Ohm@100MHz,+/-25%,1500mA,,SMD0603
FB7002 FB7100 = INDUCTOR: ROHS CHIP RES 0 Ohm 1/16W +/-5%
J7000 J7100 = PHONEJACK_STEREO_SW_2: Headphone Connector,4pin,SMT
J7001 J7002 J7101 J7102 = CON2_0: Speaker Connector, 2pin, SMT
MIC7000 MIC7100 = MIC
Q7000 Q7001 = MOSFET_N: MOSFET-N,WNM2016 ,20V,+/-8V,3.6A,45m Ohm@Vgs=4.5V,55m Ohm@Vgs=2.5V,66mOhm@Vgs=1.8V,SOT23
R7000 R7001 R7010 R7109 R7110 R7112 = RESISTOR_0
R7002 R7005-R7009 R7102 R7104-R7108 = RESISTOR: ROHS CHIP RES 33R 1/16W 5%
R7011 R7113 = RESISTOR_1: RES,thick film,10KOhm,+/-5%,1/16W,SMD0402
R7012 R7013 R7114 R7115 = RES_1B: ROHS CHIP RES 22Ohm 1/16W +/-5%
R7014 R7015 R7116 R7117 R7120 R7121 = RES_1B: ROHS CHIP RES 470Ohm 1/16W +/-5%
R7017 R7023 R7119 R7122 = RESISTOR: ROHS CHIP RES 1K 1/16W 5%
R7018 = RES_1B: ROHS CHIP RES 100KOhm 1/16W +/-5%
R7019 R7021 R7024 = RESISTOR: ROHS CHIP RES 30K 1/16W +/-5%
R7020 R7022 = RESISTOR: ROHS CHIP RES 62K 1/16W +/-5%
U7000 = wm8750_1: CODEC; Part_Type: 音频解码IC
U7001 U7002 = LM4990: Class D Audio AMP
C7100 = SMALL_CAP: CAP,MLCC,4.7uF,+/-10%,X5R,6.3V,SMD0603
C7101 C7103 = SMALL_CAP: CAP,MLCC,2.2uF,+/-10%,X5R,6.3V,SMD0603; Supplier: MURATA; Supplier P/N: GRM188R61C225KE15
C7102 C7109 C7110 = SMALL_CAP: CAP,MLCC,1uF,+/-10%,X5R,6.3V,SMD0402
C7114 = SMALL_CAP: CAP,MLCC,100nF,+/-10%,X7R,6.3V,SMD0402
R7103 R7111 = RESISTOR: RES,thick film,10KOhm,+/-5%,1/16W,SMD0402
U7100 = CODEC-ALC5631Q

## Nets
GND: C5100.2 C5101.2 C5102.2 C5103.1 C5104.2 C5105.2 C5200.2 C5201.2 C5202.2 C5203.1 C5204.2 C5205.2 C5206.2 C5207.2 C5208.2 C5300.2 C5301.2 C5302.2 C5303.1 C5304.2 C5305.2 C6500.1 C6501.2 C6502.2 C6503.2 C6504.1 C6505.1 C6506.1 C6509.1 C6510.1 C6513.2 C6514.2 C6515.2 C6516.2 C6517.2 C6518.2 C6520.1 C6521.1 C6522.1 C6523.2 C6524.1 C6525.2 C6526.1 C6527.1 C6528.1 C6529.1 C6530.1 C6531.1 C6533.1 C6600.2 C6601.2 C6602.2 C6603.1 C6604.1 C6605.2 C6606.2 C6608.2 C6609.2 C6610.1 C6611.1 C6616.2 C6617.2 C6618.2 C6619.2 C6620.2 C6621.2 C6622.1 C6623.1 C6625.1 C6626.1 C6627.2 C6628.2 C6629.1 C6630.1 C6631.1 C6632.1 C6633.1 C6634.1 C6635.1 C7002.2 C7003.2 C7004.1 C7005.1 C7006.1 C7007.2 C7008.1 C7010.1 C7011.1 C7012.1 C7013.1 C7014.2 C7015.1 C7016.1 C7017.1 C7019.2 C7021.2 C7022.2 C7023.2 C7024.1 C7025.1 C7028.2 C7029.2 C7100.2 C7101.2 C7102.2 C7104.2 C7105.2 C7106.2 C7107.2 C7108.2 C7111.2 C7112.2 C7113.2 C7114.2 C7115.1 C7119.1 C7120.1 C7121.2 C7122.1 C7123.1 C7124.2 C7125.2 ED6500.1 ED6501.1 ED6502.1 ED6600.1 ED6601.1 ED6602.1 ED7000.2 ED7001.2 ED7002.2 ED7003.2 ED7004.2 ED7005.2 ED7006.2 ED7007.2 ED7008.2 ED7100.2 ED7101.2 ED7102.2 ED7103.2 ED7104.2 ED7105.2 ED7106.2 ED7107.2 ED7108.2 J5200.1(GND) J5200.2(GND) J5200.3(GND) J5200.13(GND) J5200.16(GND) J5200.19(GND) J5200.22(GND) J5200.25(GND) J5200.28(GND) J5200.31(GND) J5200.41(GND) J5200.42(DBIST(GND)) J5200.44(GND) J5200.46(GND) J5200.49(GND) J5200.52(GND) J5200.55(GND) J5200.58(GND) J5200.61(GND) J5200.A1(GND) J5200.A2(GND) J5300.10(GND) J5300.13(GND) J5300.16(GND) J5300.19(GND) J5300.22(GND) J5300.25(GND) J7000.5 J7100.5 LCD5100.5(GND) LCD5100.9(GND) LCD5100.12(GND) LCD5100.15(GND) LCD5100.18(GND) LCD5100.21(GND) LCD5100.24(GND) LCD5100.27(GND) LCD5100.30(GND) LCD5100.33(GND) LCD5100.46(GND) LCD5100.47(GND) Q6500.2(E) Q6502.2(E) R5101.1 R5105.2 R5106.2 R5200.1 R5204.2 R5205.2 R5207.2 R5209.2 R5302.1 R5306.2 R5307.2 R6500.1 R6501.1 R6603.2 R7014.2 R7015.2 R7016.1 R7019.2 R7021.2 R7024.2 R7116.2 R7117.2 R7118.1 R7120.2 R7121.2 T5101.1 T5200.1 T5313.1 T7003.1 T7103.1 U5100.2(GND) U5101.3(GND) U5200.2(GND) U5201.3(GND) U5300.2(GND) U5301.3(GND) U6500.9(GND) U6500.34(GND) U6500.35(GND) U6500.36(GND) U6500.37(GND) U6500.38(GND) U6500.39(GND) U6500.40(GND) U6500.41(GND) U6500.42(GND) U6500.43(GND) U6500.44(GND) U6500.45(GND) U6500.46(GND) U6500.47(GND) U6500.50(GND) U6500.51(GND) U6500.52(GND) U6500.53(GND) U6500.54(GND) U6500.55(GND) U6500.56(GND) U6500.57(GND) U6500.58(GND) U6500.59(GND) U6500.60(GND) U6500.61(GND) U6500.63(GND) U6500.64(GND) U6500.65(GND) U6500.66(GND) U6500.67(GND) U6500.68(GND) U6500.73(GND) U6500.74(GND) U6500.75(GND) U6500.76(GND) U6500.77(GND) U6500.78(GND) U6500.84(GND) U6500.85(GND) U6500.86(GND) U6500.87(GND) U6500.88(GND) U6500.89(GND) U6500.90(GND) U6500.91(GND) U6500.92(GND) U6500.93(GND) U6500.94(GND) U6500.95(GND) U6500.96(GND) U6500.97(GND) U6500.98(GND) U6500.99(GND) U6500.102(GND) U6500.H1(1) U6500.H2(2) U6500.H3(3) U6500.H4(4) U6500.H5(5) U6500.H6(6) U6500.H7(7) U6500.H8(8) U6500.H9(9) U6500.H10(10) U6500.H11(11) U6500.H12(12) U6500.H13(13) U6500.H14(14) U6500.H15(15) U6500.H16(16) U6500.H17(17) U6500.H18(18) U6500.H19(19) U6500.H20(20) U6500.H21(21) U6500.H22(22) U6500.H23(23) U6500.H24(24) U6500.H25(25) U6500.H26(26) U6500.H27(27) U6500.H28(28) U6500.H29(29) U6500.H30(30) U6500.H31(31) U6500.H32(32) U6500.H33(33) U6500.H34(34) U6500.H35(35) U6500.H36(36) U6500.H37(37) U6500.H38(38) U6500.H39(39) U6500.H40(40) U6500.H41(41) U6500.H42(42) U6500.H43(43) U6500.H44(44) U6500.H45(45) U6501.2(GND) U6502.4(SIO) U6502.7(PAD0) U6502.8(PAD1) U6502.9(PAD2) U6502.10(PAD3) U6503.12(DGND) U6503.24(AGND2) U6503.28(AGND) U6503.33(GNDPAD) U6504.2(GND) U6600.4(SIO) U6600.7(PAD0) U6600.8(PAD1) U6600.9(PAD2) U6600.10(PAD3) U6601.1(GND1) U6601.13(GND2) U6601.21(GND3) U6601.22(GND4) U6601.23(GND5) U6601.26(GND6) U6601.27(GND8) U6601.28(GND9) U6601.29(GND10) U6601.30(GND11) U6601.31(GND12) U6601.32(GND13) U6601.34(GND14) U6601.35(GND15) U6601.36(GND16) U6601.39(GND17) U6601.40(GND18) U6601.41(GND19) U6601.42(GND20) U6601.44(GND21) U6601.46(GND22) U6601.H1 U6601.H2 U6601.H3 U6601.H4 U6601.H5 U6601.H6 U6601.H7 U6601.H8 U6601.H9 U6601.H10 U6601.H11 U6601.H12 U6601.H13 U6601.H14 U6601.H15 U6601.H16 U6601.H17 U6601.H18 U6601.H19 U6601.H20 U6601.H21 U6601.H22 U6601.H23 U6601.H24 U6601.H25 U6601.H26 U6601.H27 U6601.H28 U6601.H29 U6601.H30 U6601.H31 U6601.H32 U6601.H33 U6601.H34 U6601.H35 U6601.H36 U6601.H37 U6601.H38 U6601.H39 U6601.H40 U6601.H41 U6601.H42 U6601.H43 U6601.H44 U6601.H45 U6602.2(GND) U6603.12(DGND) U6603.24(AGND2) U6603.28(AGND) U6603.33(GNDPAD) U6604.2(GND) U7000.4(DGND) U7000.13(HPGND) U7000.18(AGND) U7000.25(NC) U7000.26(CE) U7000.29 U7001.7(GND) U7002.7(GND) U7100.1(SPKGND) U7100.18(AGND) U7100.22(CPREE) U7100.25(CPGND) U7100.41(DGND) U7100.49(DGND) ; also on sheet 5 6 7 8 9 10 11 12 13 14 15 16 17 18 19 20 21 22 23 24 25 26 27 35 36 37 38 39 40 41 42 43 44 45 46 47 48
VCC18_LCD: C5204.1 C5205.1 J5200.39(VDDIO) J5200.40(VDDIO) T5217.1 ; also on sheet 10 13 14
VCC_3G: C6605.1 C6606.1 Q6501.2(SOURCE) R6508.1 U6500.10(VBAT_M) U6500.11(VBAT_M) U6500.12(VBAT_M) U6500.13(VBAT_M) U6500.14(VBAT_M) U6500.69(VBAT_M1) U6500.70(VBAT_M1) U6500.71(VBAT_M1) U6500.72(VBAT_M1) U6601.10(VBAT_BB1) U6601.11(VBAT_BB2) U6601.12(VBAT_BB3) U6601.24(VBAT_3G1) U6601.25(VBAT_3G2) U6601.37(VBAT_2G1) U6601.38(VBAT_2G2) U6601.45(VBAT_USB) ; also on sheet 13 14
VCC_18: R6609.1 R7004.1 R7101.1 ; also on sheet 13 14 17 18 19 20 35 45 46
VCC_IO: C6520.2 C6625.2 R7003.1 R7100.1 R7103.1 U6504.1(IN) U6604.1(IN) ; also on sheet 11 13 14 21 22 23 24 35 41 42 43
VCC_LCD: C5104.1 C5105.1 C5304.1 C5305.1 J5300.2(AVDD) J5300.3(AVDD) LCD5100.1(VDD) LCD5100.2(VDD) LCD5100.3(VDD) R5100.2 T5100.1 T5300.1 U5101.5(VCC) U5201.5(VCC) U5301.5(VCC) ; also on sheet 5 10 13 14 27
VCC_LEDA: C5102.1 C5200.1 C5300.1 D5100.2(K) D5200.2(K) D5300.2(K) J5200.10(VLED) J5200.11(VLED) J5300.39(VLED) J5300.40(VLED) LCD5100.43(VLED) LCD5100.44(VLED) LCD5100.45(VLED) T5113.1 T5201.1 T5315.1 U5100.5(OV) U5200.5(OV) U5300.5(OV) ; also on sheet 27
VCC_LEDK: J5200.4(VLED_GND) J5200.5(VLED_GND) J5200.6(VLED_GND) J5200.7(VLED_GND) J5200.8(VLED_GND) J5200.9(VLED_GND) J5300.32(VLED_GND) J5300.33(VLED_GND) J5300.34(VLED_GND) J5300.35(VLED_GND) J5300.36(VLED_GND) J5300.37(VLED_GND) LCD5100.34(FB1) LCD5100.35(FB2) LCD5100.36(FB3) LCD5100.37(FB4) LCD5100.38(FB5) R5102.2 R5105.1 R5106.1 R5201.2 R5204.1 R5205.1 R5303.2 R5306.1 R5307.1 T5112.1 T5202.1 T5314.1 ; also on sheet 27
VCC_SPK: C7112.1 C7113.1 FB7100.2 U7100.44(SPKVDD_R) U7100.47(SPKVDD_L) ; also on sheet 35
VCC_SYS: C5100.1 C5101.1 C5201.1 C5202.1 C5206.1 C5207.1 C5208.1 C5301.1 C5302.1 C7022.1 C7111.1 FB7002.1 FB7100.1 J5200.34(VBAT) J5200.35(VBAT) J5200.36(VBAT) J5200.37(VBAT) L5100.1 L5200.1 L5300.1 T5215.1 U5100.6(IN) U5200.6(IN) U5300.6(IN) ; also on sheet 13 14 24 27 35 43
VCCA_CODEC: C6509.2 C6510.2 C6622.2 C6623.2 C7004.2 C7005.2 C7104.1 C7105.1 C7106.1 R7011.1 U6503.26(AVDD2) U6503.31(AVDD) U6603.26(AVDD2) U6603.31(AVDD) U7000.16(HPVDD) U7000.17(AVDD) U7100.16(AVDD) U7100.23(CPVDD) ; also on sheet 13 14 35
VCCIO_CODEC: C6632.2 C6633.2 C7006.2 C7107.1 C7108.1 R7000.1 R7001.1 R7003.2 R7004.2 R7100.2 R7101.2 R7109.1 R7110.1 U6603.13(DCVDD) U6603.14(DBVDD) U7000.2(DVDD) U7000.3(PVDD) U7100.39(DCVDD) U7100.40(DBVDD) ; also on sheet 11 35
VCCIO_PMU: R7023.1 R7122.1 ; also on sheet 6 11 13 14 17 18 19 20 24 35 41 43 46
VCCIO_RF: C6521.2 C6522.2 C6524.2 C6626.2 R6523.2 R6609.2 R6617.1 U6503.13(DCVDD) U6503.14(DBVDD) U6504.5(OUT) U6604.5(OUT) ; also on sheet 11
3G_DISABLE: R6514.2 ; also on sheet 11
3G_GPIO0: R6509.1 R6604.2 ; also on sheet 11
3G_GPIO1: R6605.2 ; also on sheet 11
3G_IN_L: C6506.2 C6507.1 C6508.2 C6611.2 C6612.1 C6615.2 ; also on sheet 35
3G_IN_R: C6505.2 C6507.2 C6519.2 C6610.2 C6612.2 C6624.2 ; also on sheet 35
3G_OUT_N: C6512.1 C6515.1 C6516.1 C6614.1 C6618.1 C6619.1 ; also on sheet 35
3G_OUT_P: C6511.1 C6517.1 C6518.1 C6613.1 C6620.1 C6621.1 ; also on sheet 35
3G_PWR: R6517.1 R6607.1 R6611.1 ; also on sheet 11 13 14
3G_REG_ON: R6504.1 ; also on sheet 11
3G_VCDT: R6505.1 U6500.18(VCDT)
3G_WAKEUP_IN: R6510.1 R6523.1 R6606.1 R6617.2 ; also on sheet 11
3G_WAKEUP_OUT: R6502.1 U6601.60(WAKEUP_AP) ; also on sheet 11
#W_Disable: R6507.1 U6500.19(#W_Disable)
ASM_ANT: C6531.2 C6532.2 U6500.62(ASM_ANT)
ASM_ANT_2: C6532.1 C6533.2 U6501.1(ANT)
BL_EN: R5101.2 R5200.2 R5302.2 U5100.4(EN) U5200.4(EN) U5300.4(EN) ; also on sheet 11 14 27
CABC_EN: R5108.2 R5308.2 ; also on sheet 11
DAICLK: R6519.2 U6500.79(DAICLK)
DAICLK (page 66.3G-UNA LITE (option)): R6613.2 U6601.20(DAICLK)
DAIPCMIN: R6521.2 U6500.83(DAIPCMIN)
DAIPCMIN (page 66.3G-UNA LITE (option)): R6615.2 U6601.18(DAIPCMIN)
DAIPCMOUT: R6522.2 U6500.81(DAIPCMOUT)
DAIPCMOUT (page 66.3G-UNA LITE (option)): R6616.2 U6601.19(DAIPCMOUT)
DAIRST: T6500.1 U6500.82(DAIRST)
DAISYNC: R6520.2 U6500.80(DAISYNC)
DAISYNC (page 66.3G-UNA LITE (option)): R6614.2 U6601.17(DAISYNC)
DL_Key: R6603.1 U6601.48(DL_Key)
HOST2_DM: U6500.8(USB_DM) U6601.57(USB_DM) ; also on sheet 46
HOST2_DP: U6500.7(USB_DP) U6601.58(USB_DP) ; also on sheet 46
HP_DET: C7014.1 C7121.1 R7017.2 R7023.2 R7119.2 R7122.2 ; also on sheet 11 35
HPO_L: C7118.2 R7115.2 U7100.29(HPO_L)
HPO_R: C7117.2 R7114.2 U7100.28(HPO_R)
HPOL: EC7001.1 R7020.2 U7000.15(LOUT1)
HPOR: EC7000.1 R7022.2 U7000.14(ROUT1)
I2C2_SCL_AUDIO: R7001.2 R7110.2 U6503.16(SCLK) U6603.16(SCLK) U7000.28(SCLK) U7100.35(SCL) ; also on sheet 11 35
I2C2_SDA_AUDIO: R7000.2 R7109.2 U6503.17(SDA) U6603.17(SDA) U7000.27(SDIN) U7100.34(SDA) ; also on sheet 11 35
I2C4_SCL_TP: R5300.1 T5301.1 ; also on sheet 11 36 37 38 39
I2C4_SDA_TP: R5301.1 T5302.1 ; also on sheet 11 36 37 38 39
I2S0_CLK: R6518.2 R6612.2 R7002.1 R7102.1 ; also on sheet 11 35
I2S0_LRCK_RX: R7008.1 R7106.1 ; also on sheet 11 35
I2S0_LRCK_TX: R7007.1 R7105.1 ; also on sheet 11 35
I2S0_SCLK: R7005.1 R7104.1 ; also on sheet 11 35
I2S0_SDI: R7009.1 R7108.1 ; also on sheet 11 35
I2S0_SDO0: R7006.1 R7107.1 ; also on sheet 11 35
I2S_ADCDAT: R7108.2 U7100.31(ADCDAT)
I2S_BCLK: R7104.2 U7100.32(BCLK)
I2S_DACDAT: R7107.2 U7100.30(DACDAT)
I2S_LRCK: R7105.2 R7106.2 U7100.33(LRCK)
I2S_MCLK: R7102.2 U7100.36(MCLK)
LCD_EN: R5206.2 ; also on sheet 11 14
LCD_EN_MIPI: J5200.32(EN) R5206.1 R5207.1 T5214.1
LCD_PWM_OUT: LCD5100.40(PWM_OUT) R5110.1 U5101.2(A)
LCD_PWM_OUT_N: C5103.2 R5103.2 R5104.1 R5109.2 R5110.2
LCD_RST: R5208.2 ; also on sheet 11
LCD_RST_MIPI: J5200.45(RESET) R5208.1 R5209.1 T5218.1
LCDC_BL: R5103.1 R5107.1 R5202.1 R5304.1 R5309.1 ; also on sheet 11 27
LVDS_CLK0N: J5300.17(CLKIN-) T5309.1 ; also on sheet 10
LVDS_CLK0P: J5300.18(CLKIN+) T5310.1 ; also on sheet 10
LVDS_D0N: J5300.8(RIN0-) T5303.1 ; also on sheet 10
LVDS_D0P: J5300.9(RIN0+) T5304.1 ; also on sheet 10
LVDS_D1N: J5300.11(RIN1-) T5305.1 ; also on sheet 10
LVDS_D1P: J5300.12(RIN1+) T5306.1 ; also on sheet 10
LVDS_D2N: J5300.14(RIN2-) T5307.1 ; also on sheet 10
LVDS_D2P: J5300.15(RIN2+) T5308.1 ; also on sheet 10
LVDS_D3N: J5300.20(RIN3-) T5311.1 ; also on sheet 10
LVDS_D3P: J5300.21(RIN3+) T5312.1 ; also on sheet 10
LVDS_PWM_OUT: J5300.30(LED_PWM(O)) R5311.1 U5301.2(A)
LVDS_PWM_OUT_N: C5303.2 R5304.2 R5305.1 R5310.2 R5311.2
MAIN_ANT_2: C6607.2 C6609.1 U6602.1(ANT)
MIC1N: C7110.1 C7116.1 C7120.2 ED7104.1 MIC7100.2 R7118.2
MIC1P: C7109.1 C7116.2 C7119.2 ED7103.1 MIC7100.1 R7112.1
MIC_IN1N: C7001.2 C7009.1 C7013.2 ED7004.1 MIC7000.2 R7016.2
MIC_IN1P: C7000.2 C7009.2 C7012.2 ED7003.1 MIC7000.1 R7010.1
MICBIAS1: R7113.1 U7100.7(MICBIAS1) ; also on sheet 35
MIPI_PWM_OUT: J5200.14(PWM) R5211.1 U5201.2(A)
MIPI_PWM_OUT_N: C5203.2 R5202.2 R5203.1 R5210.2 R5211.2
MIPI_TX/RX_CLKN: J5200.24(DSI_R_CLKN) T5209.1 ; also on sheet 10 25
MIPI_TX/RX_CLKP: J5200.23(DSI_R_CLKP) T5208.1 ; also on sheet 10 25
MIPI_TX/RX_D0N: J5200.27(DSI_R_0N) T5211.1 ; also on sheet 10 25
MIPI_TX/RX_D0P: J5200.26(DSI_R_0P) T5210.1 ; also on sheet 10 25
MIPI_TX/RX_D1N: J5200.21(DSI_R_1N) T5207.1 ; also on sheet 10 25
MIPI_TX/RX_D1P: J5200.20(DSI_R_1P) T5206.1 ; also on sheet 10 25
MIPI_TX/RX_D2N: J5200.18(DSI_R_2N) T5205.1 ; also on sheet 10 25
MIPI_TX/RX_D2P: J5200.17(DSI_R_2P) T5204.1 ; also on sheet 10 25
MIPI_TX/RX_D3N: J5200.30(DSI_R_3N) T5213.1 ; also on sheet 10 25
MIPI_TX/RX_D3P: J5200.29(DSI_R_3P) T5212.1 ; also on sheet 10 25
MIPI_TX_CLKN: J5200.54(DSI_L_CLKN) LCD5100.25(MIPI_CLKN) T5106.1 T5224.1 ; also on sheet 10
MIPI_TX_CLKP: J5200.53(DSI_L_CLKP) LCD5100.26(MIPI_CLKP) T5107.1 T5223.1 ; also on sheet 10
MIPI_TX_D0N: J5200.57(DSI_L_0N) LCD5100.28(MIPI_0N) T5108.1 T5226.1 ; also on sheet 10
MIPI_TX_D0P: J5200.56(DSI_L_0P) LCD5100.29(MIPI_0P) T5109.1 T5225.1 ; also on sheet 10
MIPI_TX_D1N: J5200.51(DSI_L_1N) LCD5100.22(MIPI_1N) T5104.1 T5222.1 ; also on sheet 10
MIPI_TX_D1P: J5200.50(DSI_L_1P) LCD5100.23(MIPI_1P) T5105.1 T5221.1 ; also on sheet 10
MIPI_TX_D2N: J5200.48(DSI_L_2N) LCD5100.19(MIPI_2N) T5102.1 T5220.1 ; also on sheet 10
MIPI_TX_D2P: J5200.47(DSI_L_2P) LCD5100.20(MIPI_2P) T5103.1 T5219.1 ; also on sheet 10
MIPI_TX_D3N: J5200.60(DSI_L_3N) LCD5100.31(MIPI_3N) T5110.1 T5228.1 ; also on sheet 10
MIPI_TX_D3P: J5200.59(DSI_L_3P) LCD5100.32(MIPI_3P) T5111.1 T5227.1 ; also on sheet 10
PA_5V: C7021.1 C7023.1 C7029.1 FB7002.2 U7001.6(VDD) U7002.6(VDD)
PHE_DET: ED7102.1 J7100.2(COM) R7111.2 R7119.1 T7102.1
PHONE_CTL: R7018.2 ; also on sheet 6
PHONE_DET: ED7002.1 J7000.2(COM) R7017.1 T7002.1
POWERON: R6503.2 U6500.17(PWRKEY)
SIM_CLK: C6601.1 ED6601.2 U6600.3(CLK) U6601.6(SCLK)
SIM_RST: C6602.1 ED6602.2 U6600.2(RST) U6601.7(SRST)
SIM_SIO: C6600.1 ED6600.2 R6600.1 U6600.6(GND) U6601.5(SIO)
SIM_VCC: C6603.2 C6604.2 R6600.2 U6600.1(VSIM) U6601.15(SIM_VCC)
SPK_CTL: R7024.1 U7001.1(EN) U7002.1(EN) ; also on sheet 11
SPO_LN: FB7103.1 U7100.46(SPO_LN)
SPO_LP: FB7101.1 U7100.48(SPO_LP)
SPO_RN: FB7104.1 U7100.45(SPO_RN)
SPO_RP: FB7102.1 U7100.43(SPO_RP)
U0RXD: T6600.1 U6601.61(U0TXD)
U0TXD: T6601.1 U6601.62(U0RXD)
UART1_CTS: U6601.49(U1RTS) ; also on sheet 11
UART1_RTS: R6602.1 ; also on sheet 11
UART1_RX: R6511.2 U6601.52(U1TXD) ; also on sheet 11
UART1_TX: R6513.2 R6601.1 ; also on sheet 11
UIM_CLK: C6502.1 ED6501.2 U6500.23(SCLK) U6502.3(CLK)
UIM_DAT: C6501.1 ED6500.2 R6506.1 U6500.21(SIO) U6502.6(GND)
UIM_PWR: C6500.2 C6504.2 R6506.2 U6500.20(VSIM_PMU) U6502.1(VSIM)
UIM_RST: C6503.1 ED6502.2 U6500.22(SRST) U6502.2(RST)
N60731272: D5100.1(A) L5100.2 U5100.1(SW)
N60731274: R5102.1 R5104.2 U5100.3(FB)
N60732138: LCD5100.6(BIST) R5100.1
N60886140: J5200.15(TE) T5203.1
N60886148: J5200.43(TE_S) T5216.1
N60899992: J5300.5(I2C_CLK_EDID) R5300.2
N60900000: J5300.6(I2C_SDA_EDID) R5301.2
N60900327: D5300.1(A) L5300.2 U5300.1(SW)
N60900329: R5303.1 R5305.2 U5300.3(FB)
N61304557: D5200.1(A) L5200.2 U5200.1(SW)
N61304559: R5201.1 R5203.2 U5200.3(FB)
N62000856: R7009.2 U7000.8(ADCDAT)
N62000857: C7007.1 U7000.10(VREF)
N62000874: C7003.1 U7000.19(ADCVREF)
N62000875: C7002.1 U7000.20(VMID)
N62000882: R7002.2 U7000.1(MCLK)
N62000884: R7005.2 U7000.5(BCLK)
N62000885: R7006.2 U7000.6(DACDAT)
N62000887: R7007.2 R7008.2 U7000.7(LRCK)
N62000893: C7000.1 U7000.22(LIN1)
N62000894: C7001.1 U7000.21(RIN1)
N62000910: C7016.2 U7001.2(BYPASS)
N62000916: C7018.2 U7001.3(IN+)
N62000917: C7018.1 R7019.1
N62000918: C7017.2 ED7005.1 FB7000.2 J7001.1
N62000920: C7019.1 ED7006.1 FB7001.2 J7001.2
N62000923: C7020.1 R7020.1
N62000924: C7020.2 U7001.4(IN-)
N62000927: FB7001.1 U7001.5(VO1)
N62000928: FB7000.1 U7001.8(VO2)
N62000930: C7010.2 ED7000.1 J7000.1(R) R7013.1 T7000.1
N62000931: C7011.2 ED7001.1 J7000.4(L) R7012.1 T7001.1
N62000940: C7015.2 Q7000.1(GATE) Q7001.1(GATE) R7018.1
N62000945: EC7001.2 Q7001.3(DRAIN) R7015.1
N62000956: EC7000.2 Q7000.3(DRAIN) R7014.1
N62000961: Q7000.2(SOURCE) R7012.2
N62000964: Q7001.2(SOURCE) R7013.2
N62000985: C7008.2 R7010.2 R7011.2
N62001033: C7028.1 ED7008.1 FB7004.2 J7002.2
N62001034: C7025.2 ED7007.1 FB7003.2 J7002.1
N62001035: FB7004.1 U7002.5(VO1)
N62001036: FB7003.1 U7002.8(VO2)
N62001038: C7027.1 R7022.1
N62001047: C7024.2 U7002.2(BYPASS)
N62001048: C7026.2 U7002.3(IN+)
N62001054: C7026.1 R7021.1
N62001058: C7027.2 U7002.4(IN-)
N62017504: C7122.2 ED7105.1 FB7101.2 J7101.1
N62017506: C7124.1 ED7106.1 FB7103.2 J7101.2
N62017511: ED7100.1 J7100.1(R) R7115.1 R7117.1 T7100.1
N62017512: ED7101.1 J7100.4(L) R7114.1 R7116.1 T7101.1
N62017546: C7115.2 R7112.2 R7113.2
N62017576: C7125.1 ED7108.1 FB7104.2 J7102.2
N62017577: C7123.2 ED7107.1 FB7102.2 J7102.1
N62017607: C7118.1 R7121.1
N62017608: C7117.1 R7120.1
N62017641: R7111.1 U7100.37(DMIC_SDA/GPIO)
N62017642: C7109.2 U7100.12(MIC1P)
N62017643: C7110.2 U7100.13(MIC1N)
N62017646: C7103.2 U7100.26(CBN)
N62017648: C7101.1 U7100.27(CPVEE)
N62017649: C7100.1 U7100.17(VREF)
N62017655: C7102.1 U7100.21(Cdepop)
N62017682: C7114.1 R7103.2 U7100.42(~{RST})
N62017688: C7103.1 U7100.24(CBP)
N62042115: C6613.2 R6608.1
N62042134: C6614.2 R6610.1
N62045548: C6629.2 C6630.2 U6603.27(VREF)
N62076362: T6502.1 U6500.101(SDA)
N62076363: T6501.1 U6500.100(SCL)
N62076378: Q6500.1(B) R6504.2
N62076384: R6502.2 U6500.6(Wake)
N62076403: T6504.1 U6500.26(KROW0)
N62076404: T6503.1 U6500.25(KCOL6)
N62076410: R6510.2 U6500.29(#EINT9)
N62076413: R6509.2 U6500.27(AP_Ready)
N62076419: R6511.1 U6500.33(UTXD2)
N62076420: R6513.1 U6500.32(URXD2)
N62076423: T6506.1 U6500.31(URXD1)
N62076425: T6505.1 U6500.30(UTXD1)
N62076536: R6500.2 U6500.1(#Sys_config)
N62076543: R6501.2 U6500.5(ID)
N62076556: Q6500.3(C) R6503.1
N62076637: Q6501.1(GATE) R6508.2 R6512.1
N62076641: Q6502.1(B) R6514.1
N62076644: Q6501.3(DRAIN) R6505.2 R6507.2
N62085839: C6607.1 C6608.1 U6601.33(MAIN_ANT)
N62097916: C6627.1 R6611.2 U6604.3(EN)
N62227693: R6606.2 U6601.8(WAKEUP_MODEM)
N62227695: R6607.2 U6601.14(POWERON)
N62227848: R6605.1 U6601.47(#EINT0)
N62227851: R6601.2 U6601.50(U1RXD)
N62227853: R6602.2 U6601.51(U1CTS)
N62227866: R6604.1 U6601.59(GPIO0)
N62227915: C6631.2 U6603.18(CDEPOP)
N62227916: C6634.2 R6614.1 U6603.7(LRCK)
N62227921: C6616.1 R6610.2 U6603.25(LIN_OUT_N)
N62227924: R6616.1 U6603.10(DACDAT)
N62227932: C6624.1 U6603.6(LINE_IN_R)
N62227933: C6615.1 U6603.3(LINE_IN_L)
N62227935: C6635.2 R6613.1 U6603.8(BCLK)
N62227943: R6615.1 U6603.9(ADCDAT)
N62227945: C6617.1 R6608.2 U6603.23(LIN_OUT)
N62227949: R6612.1 U6603.11(MCLK)
N62311817: C6511.2 R6516.1
N62311819: C6512.2 R6515.1
N62311845: C6526.2 C6527.2 U6503.27(VREF)
N62311917: C6528.2 U6503.18(CDEPOP)
N62311919: C6529.2 R6520.1 U6503.7(LRCK)
N62311929: C6513.1 R6515.2 U6503.25(LIN_OUT_N)
N62311935: R6522.1 U6503.10(DACDAT)
N62311951: C6519.1 U6503.6(LINE_IN_R)
N62311953: C6508.1 U6503.3(LINE_IN_L)
N62311957: C6530.2 R6519.1 U6503.8(BCLK)
N62311973: R6521.1 U6503.9(ADCDAT)
N62311977: C6514.1 R6516.2 U6503.23(LIN_OUT)
N62311985: R6518.1 U6503.11(MCLK)
N62749549: C6525.1 R6517.2 U6504.3(EN)
N63858202: R5109.1 U5101.4(Y)
N63860037: Q6502.3(C) R6512.2
N63884248: LCD5100.41(CABC_EN) R5108.1
N63884356: J5300.28(CABC_EN) R5308.1
N63885917: LCD5100.39(PWM_IN) R5107.2
N63886349: J5300.29(LED_PWM(I)) R5309.2
N63886721: R5310.1 U5301.4(Y)
N63886973: R5210.1 U5201.4(Y)
N64091891: C6628.1 U6604.4(BP)
N64092533: C6523.1 U6504.4(BP)

Not connected (* = marked no-connect by the designer): J5200 12(NC)* 33(NC)* 38(NC)*; J5300 1(NC)* 4(NC)* 7(NC)* 23(NC)* 24(NC)* 26(NC)* 27(Color_EN)* 31(NC)* 38(NC)*; J7000 3(HP)*; J7100 3(HP)*; LCD5100 4(NC)* 7(NC)* 8(NC)* 10(NC)* 11(NC)* 13(NC)* 14(NC)* 16(NC)* 17(NC)* 42(NC)*; U5101 1(NC)*; U5201 1(NC)*; U5301 1(NC)*; U6500 2(GPIO0) 3(GPIO1) 4(GPIO2) 15(NC)* 16(NC)* 24(NC)* 28(NC)* 48(NC)* 49(NC)* 103(NC)* 104(NC)*; U6502 5(NC)*; U6503 1(MICIP)* 2(MICIN)* 4(MIC2P)* 5(MIC2N)* 15(GPIO)* 19(AUXIN_L)* 20(AUXIN_R)* 21(AUXOUT_L)* 22(AUXOUT_R)* 29(HP_OUT_R)* 30(HP_OUT_L)* 32(MICBAS)*; U6600 5(NC)*; U6601 2(RESERVE)* 3(RESERVE)* 4(RESERVE)* 9(NC1)* 16(RESERVE)* 43(DIV_ANT)* 53(VDD_UART)* 54(RESERVE)* 55(RESERVE)* 56(RESERVE)* 63(RESERVE)* 64(RESERVE)* 65(RESERVE)* 66(RESERVE)*; U6603 1(MICIP)* 2(MICIN)* 4(MIC2P)* 5(MIC2N)* 15(GPIO)* 19(AUXIN_L)* 20(AUXIN_R)* 21(AUXOUT_L)* 22(AUXOUT_R)* 29(HP_OUT_R)* 30(HP_OUT_L)* 32(MICBAS)*; U7000 9(NC)* 11(NC)* 12(NC)* 23(NC)* 24(NC)*; U7100 2(ROUT_P)* 3(ROUT_N)* 4(LOUT_N)* 5(LOUT_P)* 6(MICBIAS2)* 8(AXI_L/JID1)* 9(AXI_R/JID2)* 10(BB_RXN)* 11(BB_RXP)* 14(MIC2N)* 15(MIC2P)* 19(MONO_P)* 20(MONO_N)* 38(DMIC_SCL)*

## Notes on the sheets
sheet 28
- MIPI Panel
sheet 29
- Dual MIPI Panel
- note：MIPI_TX for Left channel,and MIPI_TX/RX for right channel。
sheet 30
- LVDS Panel
sheet 31
- 3G UNA
- 1K USB+UART
  NC USB only
- 1K 850 Module
  NC 900 Module
- Support "OFF and Sleep" mode.
- For AP control :  PWRKEY_IC_0
- POWER
- CODEC
- MCLK need
  24.576MHz input
sheet 32
- 3G UNA LITE
- UART0 :
  Catch log file.
  UART1 :
  USB+UART MODE
- VBAT: 3.4~4.35V, Peak current: 1.8A
- Level of Poweron
  High >2V~5V :Power on module
  Low <0.3V:Power off module
- POWER
- CODEC
- MCLK need
  24.576MHz input
sheet 33
- CODEC
- close to ES8323
- MIC
- EARPHONE
- SPEAKER
sheet 34
- CODEC
- MIC
- EARPHONE
- SPEAKER
